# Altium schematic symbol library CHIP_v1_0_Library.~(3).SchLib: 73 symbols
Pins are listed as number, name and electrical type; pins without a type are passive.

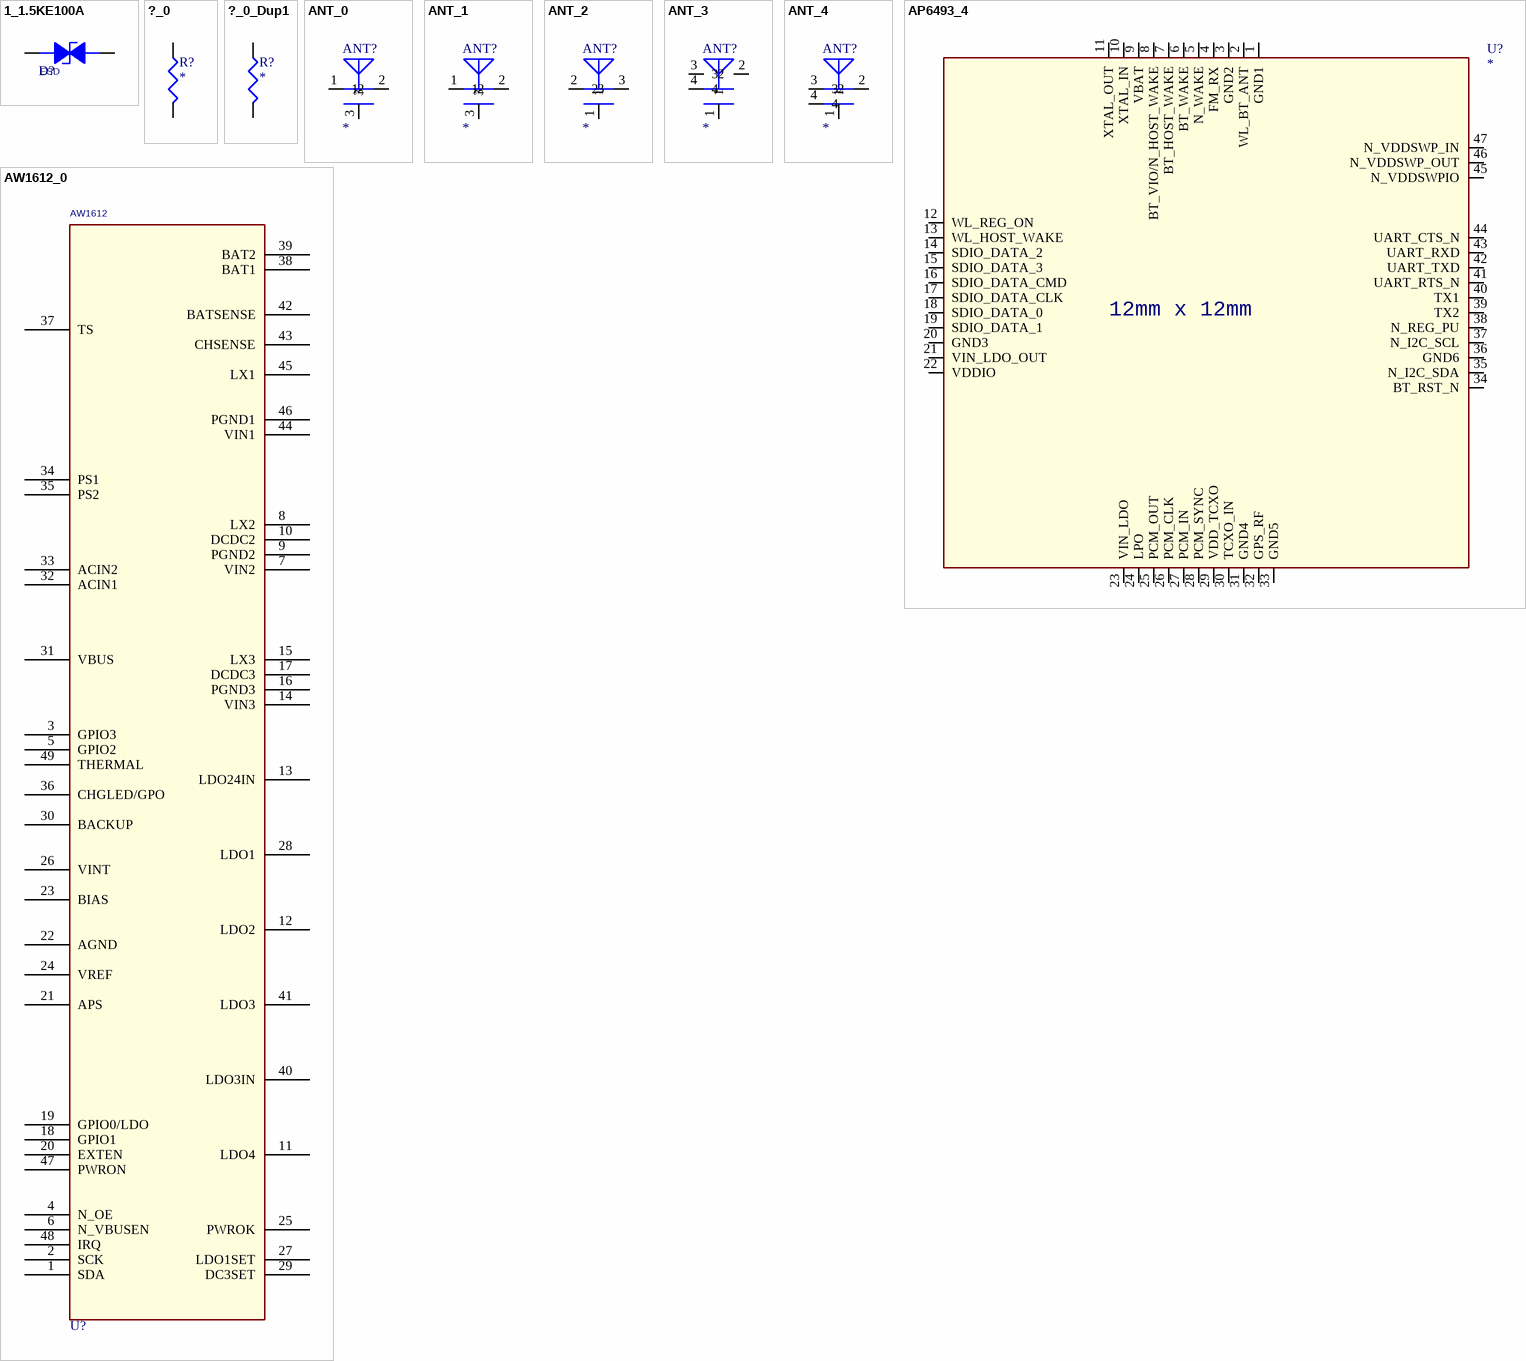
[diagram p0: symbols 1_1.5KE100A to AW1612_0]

## 1_1.5KE100A
designator D?, comment ESD
Altium-Right: 40; Altium-Bottom: 20
pins: 1 ANODE, 2 CATHODE

## ?_0
designator R?
Altium-Right: 20; Altium-Bottom: 30
footprint R0402
pins: 1, 2

## ?_0_Dup1
designator R?
Altium-Right: 20; Altium-Bottom: 30
footprint R0402
pins: 1, 2

## ANT_0
designator ANT?
Altium-Right: 20; Altium-Bottom: 30
pins: 1 (hiz), 2, 3

## ANT_1
designator ANT?
Altium-Right: 20; Altium-Bottom: 30
pins: 1, 2, 3

## ANT_2
designator ANT?
Altium-Right: 20; Altium-Bottom: 30
pins: 1, 2, 3

## ANT_3
designator ANT?
Altium-Right: 20; Altium-Bottom: 30
pins: 1, 2, 3, 4

## ANT_4
designator ANT?
Altium-Right: 20; Altium-Bottom: 30
pins: 1, 2, 3, 4

## AP6493_4
designator U?
Altium-Right: 350; Altium-Bottom: 340
pins: 1 GND1, 2 WL_BT_ANT, 3 GND2, 4 FM_RX, 5 N_WAKE, 6 BT_WAKE, 7 BT_HOST_WAKE, 8 BT_VIO/N_HOST_WAKE, 9 VBAT, 10 XTAL_IN, 11 XTAL_OUT, 12 WL_REG_ON, 13 WL_HOST_WAKE, 14 SDIO_DATA_2, 15 SDIO_DATA_3, 16 SDIO_DATA_CMD, 17 SDIO_DATA_CLK, 18 SDIO_DATA_0, 19 SDIO_DATA_1, 20 GND3, 21 VIN_LDO_OUT, 22 VDDIO, 23 VIN_LDO, 24 LPO, 25 PCM_OUT, 26 PCM_CLK, 27 PCM_IN, 28 PCM_SYNC, 29 VDD_TCXO, 30 TCXO_IN, 31 GND4, 32 GPS_RF, 33 GND5, 34 BT_RST_N, 35 N_I2C_SDA, 36 GND6, 37 N_I2C_SCL, 38 N_REG_PU, 39 TX2, 40 TX1, 41 UART_RTS_N, 42 UART_TXD, 43 UART_RXD, 44 UART_CTS_N, 45 N_VDDSWPIO, 46 N_VDDSWP_OUT, 47 N_VDDSWP_IN

## AW1612_0
designator U?, comment AW1612
Altium-Right: 130; Altium-Bottom: 730
pins: 1 SDA, 2 SCK, 3 GPIO3, 4 N_OE, 5 GPIO2, 6 N_VBUSEN, 7 VIN2, 8 LX2, 9 PGND2, 10 DCDC2, 11 LDO4, 12 LDO2, 13 LDO24IN, 14 VIN3, 15 LX3, 16 PGND3, 17 DCDC3, 18 GPIO1, 19 GPIO0/LDO, 20 EXTEN, 21 APS, 22 AGND, 23 BIAS, 24 VREF, 25 PWROK, 26 VINT, 27 LDO1SET, 28 LDO1, 29 DC3SET, 30 BACKUP, 31 VBUS, 32 ACIN1, 33 ACIN2, 34 PS1, 35 PS2, 36 CHGLED/GPO, 37 TS, 38 BAT1, 39 BAT2, 40 LDO3IN, 41 LDO3, 42 BATSENSE, 43 CHSENSE, 44 VIN1, 45 LX1, 46 PGND1, 47 PWRON, 48 IRQ, 49 THERMAL

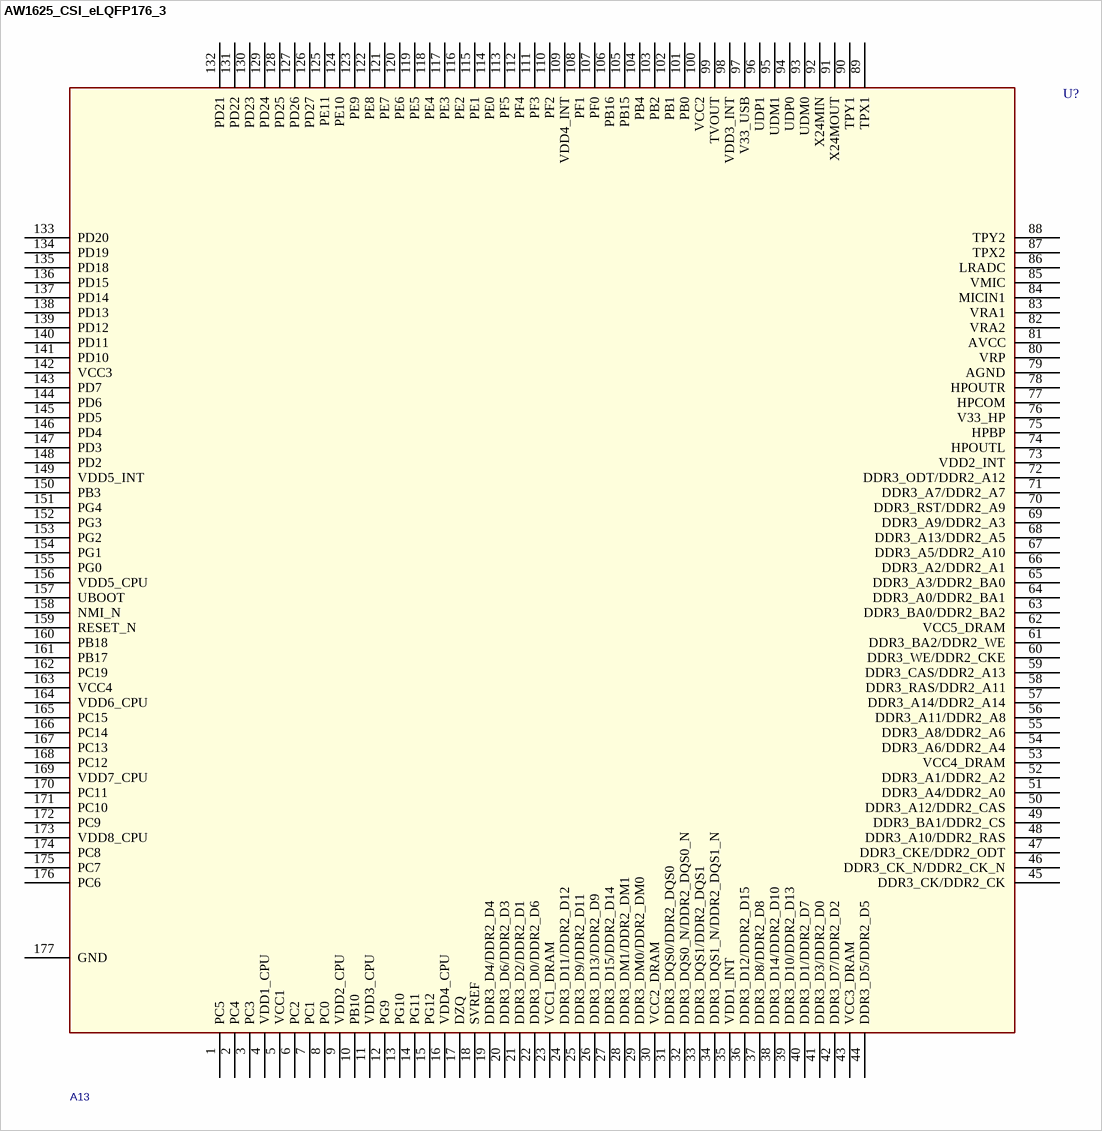
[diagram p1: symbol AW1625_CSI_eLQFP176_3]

## AW1625_CSI_eLQFP176_3
designator U?, comment A13
Altium-Right: 630
pins: 1 PC5, 2 PC4, 3 PC3, 4 VDD1_CPU, 5 VCC1, 6 PC2, 7 PC1, 8 PC0, 9 VDD2_CPU, 10 PB10, 11 VDD3_CPU, 12 PG9, 13 PG10, 14 PG11, 15 PG12, 16 VDD4_CPU, 17 DZQ, 18 SVREF, 19 DDR3_D4/DDR2_D4, 20 DDR3_D6/DDR2_D3, 21 DDR3_D2/DDR2_D1, 22 DDR3_D0/DDR2_D6, 23 VCC1_DRAM, 24 DDR3_D11/DDR2_D12, 25 DDR3_D9/DDR2_D11, 26 DDR3_D13/DDR2_D9, 27 DDR3_D15/DDR2_D14, 28 DDR3_DM1/DDR2_DM1, 29 DDR3_DM0/DDR2_DM0, 30 VCC2_DRAM, 31 DDR3_DQS0/DDR2_DQS0, 32 DDR3_DQS0_N/DDR2_DQS0_N, 33 DDR3_DQS1/DDR2_DQS1, 34 DDR3_DQS1_N/DDR2_DQS1_N, 35 VDD1_INT, 36 DDR3_D12/DDR2_D15, 37 DDR3_D8/DDR2_D8, 38 DDR3_D14/DDR2_D10, 39 DDR3_D10/DDR2_D13, 40 DDR3_D1/DDR2_D7, 41 DDR3_D3/DDR2_D0, 42 DDR3_D7/DDR2_D2, 43 VCC3_DRAM, 44 DDR3_D5/DDR2_D5, 45 DDR3_CK/DDR2_CK, 46 DDR3_CK_N/DDR2_CK_N, 47 DDR3_CKE/DDR2_ODT, 48 DDR3_A10/DDR2_RAS, 49 DDR3_BA1/DDR2_CS, 50 DDR3_A12/DDR2_CAS, 51 DDR3_A4/DDR2_A0, 52 DDR3_A1/DDR2_A2, 53 VCC4_DRAM, 54 DDR3_A6/DDR2_A4, 55 DDR3_A8/DDR2_A6, 56 DDR3_A11/DDR2_A8, 57 DDR3_A14/DDR2_A14, 58 DDR3_RAS/DDR2_A11, 59 DDR3_CAS/DDR2_A13, 60 DDR3_WE/DDR2_CKE, 61 DDR3_BA2/DDR2_WE, 62 VCC5_DRAM, 63 DDR3_BA0/DDR2_BA2, 64 DDR3_A0/DDR2_BA1, 65 DDR3_A3/DDR2_BA0, 66 DDR3_A2/DDR2_A1, 67 DDR3_A5/DDR2_A10, 68 DDR3_A13/DDR2_A5, 69 DDR3_A9/DDR2_A3, 70 DDR3_RST/DDR2_A9, 71 DDR3_A7/DDR2_A7, 72 DDR3_ODT/DDR2_A12, 73 VDD2_INT, 74 HPOUTL, 75 HPBP, 76 V33_HP, 77 HPCOM, 78 HPOUTR, 79 AGND, 80 VRP, 81 AVCC, 82 VRA2, 83 VRA1, 84 MICIN1, 85 VMIC, 86 LRADC, 87 TPX2, 88 TPY2, 89 TPX1, 90 TPY1, 91 X24MOUT, 92 X24MIN, 93 UDM0, 94 UDP0, 95 UDM1, 96 UDP1, 97 V33_USB, 98 VDD3_INT, 99 TVOUT, 100 VCC2, 101 PB0, 102 PB1, 103 PB2, 104 PB4, 105 PB15, 106 PB16, 107 PF0, 108 PF1, 109 VDD4_INT, 110 PF2, 111 PF3, 112 PF4, 113 PF5, 114 PE0, 115 PE1, 116 PE2, 117 PE3, 118 PE4, 119 PE5, 120 PE6, 121 PE7, 122 PE8, 123 PE9, 124 PE10, 125 PE11, 126 PD27, 127 PD26, 128 PD25, 129 PD24, 130 PD23, 131 PD22, 132 PD21, 133 PD20, 134 PD19, 135 PD18, 136 PD15, 137 PD14, 138 PD13, 139 PD12, 140 PD11, 141 PD10, 142 VCC3, 143 PD7, 144 PD6, 145 PD5, 146 PD4, 147 PD3, 148 PD2, 149 VDD5_INT, 150 PB3, 151 PG4, 152 PG3, 153 PG2, 154 PG1, 155 PG0, 156 VDD5_CPU, 157 UBOOT, 158 NMI_N, 159 RESET_N, 160 PB18, 161 PB17, 162 PC19, 163 VCC4, 164 VDD6_CPU, 165 PC15, 166 PC14, 167 PC13, 168 PC12, 169 VDD7_CPU, 170 PC11, 171 PC10, 172 PC9, 173 VDD8_CPU, 174 PC8, 175 PC7, 176 PC6, 177 GND

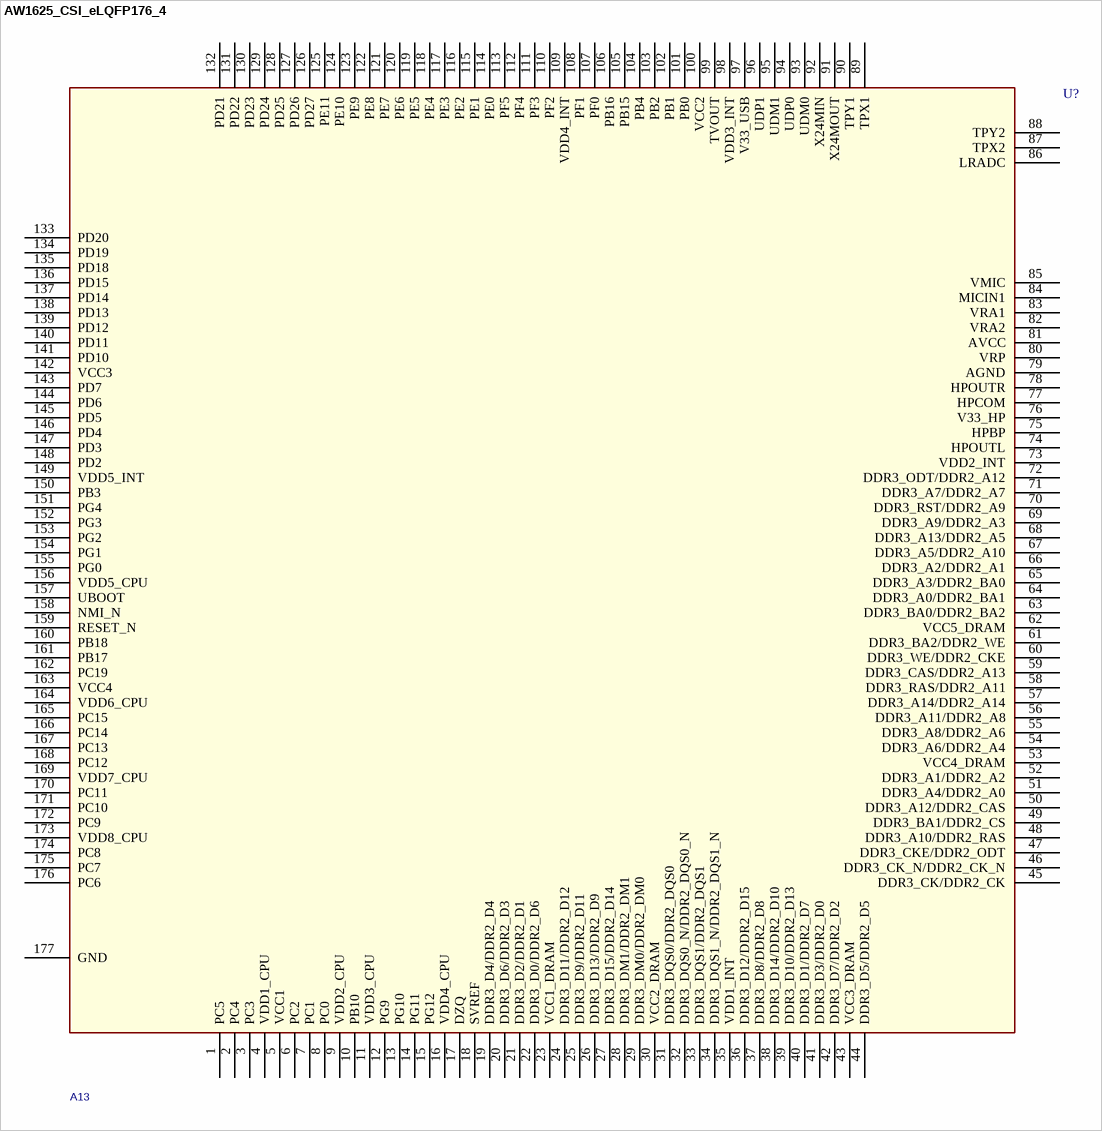
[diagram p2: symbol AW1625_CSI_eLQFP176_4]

## AW1625_CSI_eLQFP176_4
designator U?, comment A13
Altium-Right: 630
pins: 1 PC5, 2 PC4, 3 PC3, 4 VDD1_CPU, 5 VCC1, 6 PC2, 7 PC1, 8 PC0, 9 VDD2_CPU, 10 PB10, 11 VDD3_CPU, 12 PG9, 13 PG10, 14 PG11, 15 PG12, 16 VDD4_CPU, 17 DZQ, 18 SVREF, 19 DDR3_D4/DDR2_D4, 20 DDR3_D6/DDR2_D3, 21 DDR3_D2/DDR2_D1, 22 DDR3_D0/DDR2_D6, 23 VCC1_DRAM, 24 DDR3_D11/DDR2_D12, 25 DDR3_D9/DDR2_D11, 26 DDR3_D13/DDR2_D9, 27 DDR3_D15/DDR2_D14, 28 DDR3_DM1/DDR2_DM1, 29 DDR3_DM0/DDR2_DM0, 30 VCC2_DRAM, 31 DDR3_DQS0/DDR2_DQS0, 32 DDR3_DQS0_N/DDR2_DQS0_N, 33 DDR3_DQS1/DDR2_DQS1, 34 DDR3_DQS1_N/DDR2_DQS1_N, 35 VDD1_INT, 36 DDR3_D12/DDR2_D15, 37 DDR3_D8/DDR2_D8, 38 DDR3_D14/DDR2_D10, 39 DDR3_D10/DDR2_D13, 40 DDR3_D1/DDR2_D7, 41 DDR3_D3/DDR2_D0, 42 DDR3_D7/DDR2_D2, 43 VCC3_DRAM, 44 DDR3_D5/DDR2_D5, 45 DDR3_CK/DDR2_CK, 46 DDR3_CK_N/DDR2_CK_N, 47 DDR3_CKE/DDR2_ODT, 48 DDR3_A10/DDR2_RAS, 49 DDR3_BA1/DDR2_CS, 50 DDR3_A12/DDR2_CAS, 51 DDR3_A4/DDR2_A0, 52 DDR3_A1/DDR2_A2, 53 VCC4_DRAM, 54 DDR3_A6/DDR2_A4, 55 DDR3_A8/DDR2_A6, 56 DDR3_A11/DDR2_A8, 57 DDR3_A14/DDR2_A14, 58 DDR3_RAS/DDR2_A11, 59 DDR3_CAS/DDR2_A13, 60 DDR3_WE/DDR2_CKE, 61 DDR3_BA2/DDR2_WE, 62 VCC5_DRAM, 63 DDR3_BA0/DDR2_BA2, 64 DDR3_A0/DDR2_BA1, 65 DDR3_A3/DDR2_BA0, 66 DDR3_A2/DDR2_A1, 67 DDR3_A5/DDR2_A10, 68 DDR3_A13/DDR2_A5, 69 DDR3_A9/DDR2_A3, 70 DDR3_RST/DDR2_A9, 71 DDR3_A7/DDR2_A7, 72 DDR3_ODT/DDR2_A12, 73 VDD2_INT, 74 HPOUTL, 75 HPBP, 76 V33_HP, 77 HPCOM, 78 HPOUTR, 79 AGND, 80 VRP, 81 AVCC, 82 VRA2, 83 VRA1, 84 MICIN1, 85 VMIC, 86 LRADC, 87 TPX2, 88 TPY2, 89 TPX1, 90 TPY1, 91 X24MOUT, 92 X24MIN, 93 UDM0, 94 UDP0, 95 UDM1, 96 UDP1, 97 V33_USB, 98 VDD3_INT, 99 TVOUT, 100 VCC2, 101 PB0, 102 PB1, 103 PB2, 104 PB4, 105 PB15, 106 PB16, 107 PF0, 108 PF1, 109 VDD4_INT, 110 PF2, 111 PF3, 112 PF4, 113 PF5, 114 PE0, 115 PE1, 116 PE2, 117 PE3, 118 PE4, 119 PE5, 120 PE6, 121 PE7, 122 PE8, 123 PE9, 124 PE10, 125 PE11, 126 PD27, 127 PD26, 128 PD25, 129 PD24, 130 PD23, 131 PD22, 132 PD21, 133 PD20, 134 PD19, 135 PD18, 136 PD15, 137 PD14, 138 PD13, 139 PD12, 140 PD11, 141 PD10, 142 VCC3, 143 PD7, 144 PD6, 145 PD5, 146 PD4, 147 PD3, 148 PD2, 149 VDD5_INT, 150 PB3, 151 PG4, 152 PG3, 153 PG2, 154 PG1, 155 PG0, 156 VDD5_CPU, 157 UBOOT, 158 NMI_N, 159 RESET_N, 160 PB18, 161 PB17, 162 PC19, 163 VCC4, 164 VDD6_CPU, 165 PC15, 166 PC14, 167 PC13, 168 PC12, 169 VDD7_CPU, 170 PC11, 171 PC10, 172 PC9, 173 VDD8_CPU, 174 PC8, 175 PC7, 176 PC6, 177 GND

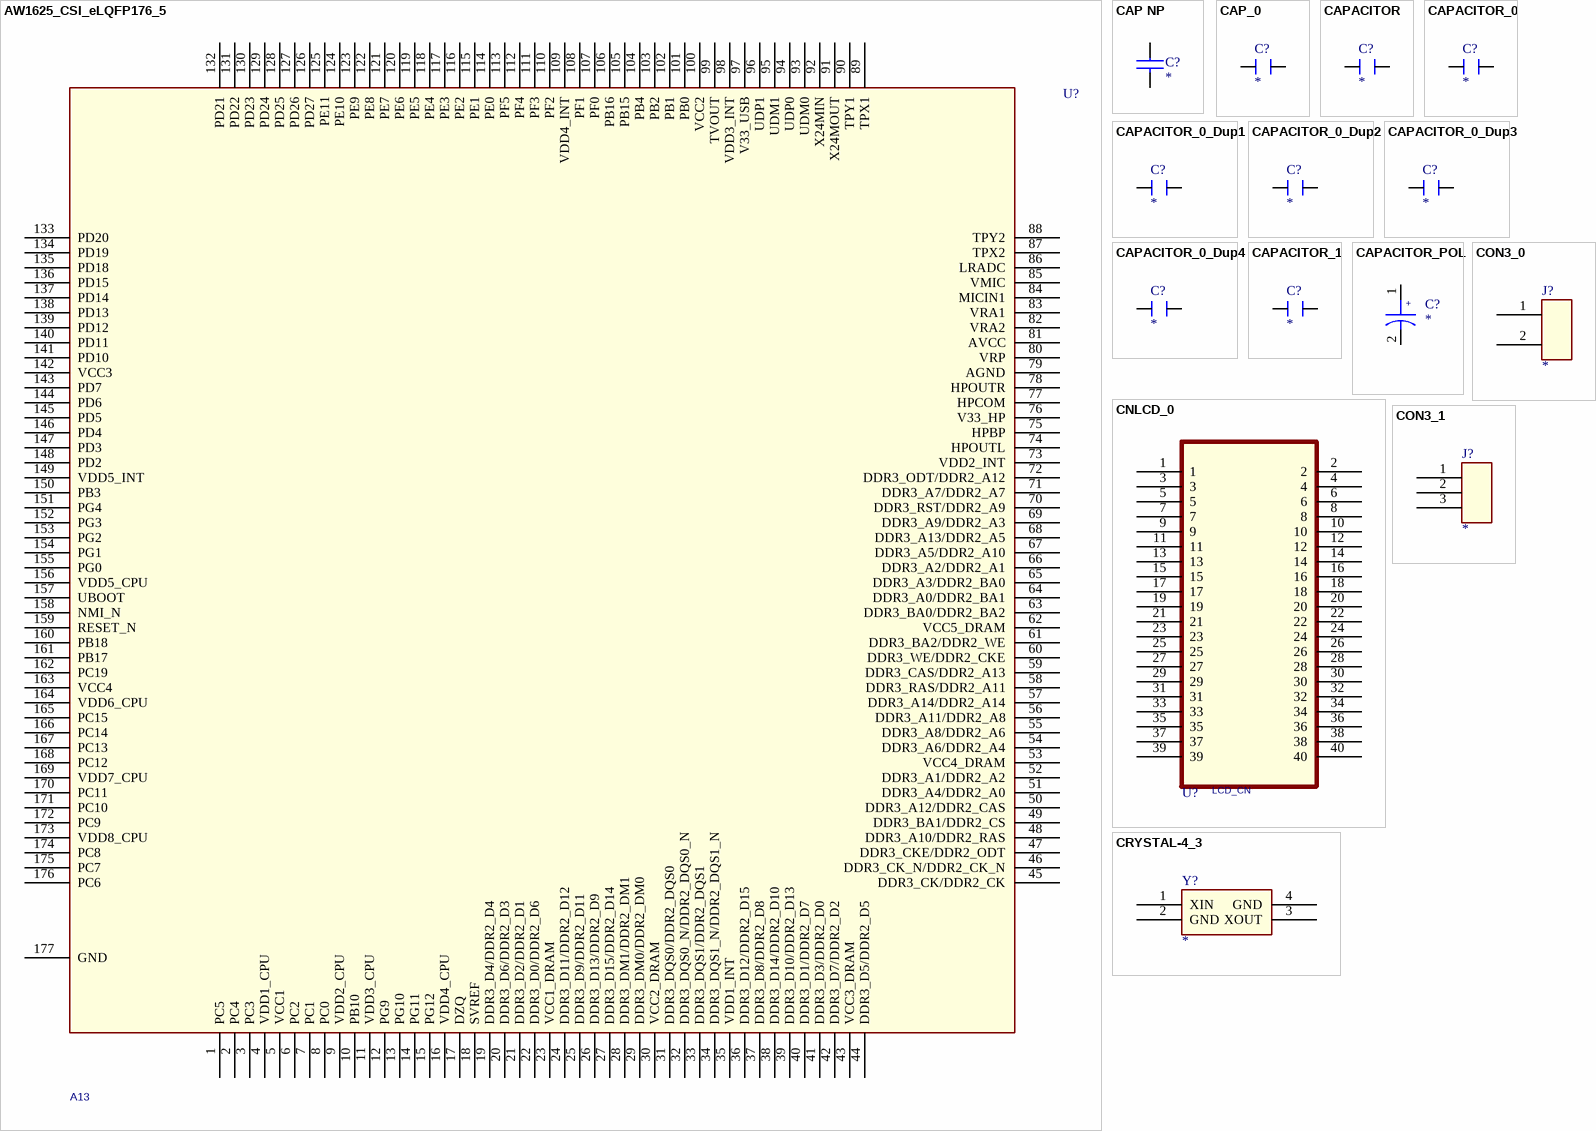
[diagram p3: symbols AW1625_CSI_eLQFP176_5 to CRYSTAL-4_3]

## AW1625_CSI_eLQFP176_5
designator U?, comment A13
Altium-Right: 630
pins: 1 PC5, 2 PC4, 3 PC3, 4 VDD1_CPU, 5 VCC1, 6 PC2, 7 PC1, 8 PC0, 9 VDD2_CPU, 10 PB10, 11 VDD3_CPU, 12 PG9, 13 PG10, 14 PG11, 15 PG12, 16 VDD4_CPU, 17 DZQ, 18 SVREF, 19 DDR3_D4/DDR2_D4, 20 DDR3_D6/DDR2_D3, 21 DDR3_D2/DDR2_D1, 22 DDR3_D0/DDR2_D6, 23 VCC1_DRAM, 24 DDR3_D11/DDR2_D12, 25 DDR3_D9/DDR2_D11, 26 DDR3_D13/DDR2_D9, 27 DDR3_D15/DDR2_D14, 28 DDR3_DM1/DDR2_DM1, 29 DDR3_DM0/DDR2_DM0, 30 VCC2_DRAM, 31 DDR3_DQS0/DDR2_DQS0, 32 DDR3_DQS0_N/DDR2_DQS0_N, 33 DDR3_DQS1/DDR2_DQS1, 34 DDR3_DQS1_N/DDR2_DQS1_N, 35 VDD1_INT, 36 DDR3_D12/DDR2_D15, 37 DDR3_D8/DDR2_D8, 38 DDR3_D14/DDR2_D10, 39 DDR3_D10/DDR2_D13, 40 DDR3_D1/DDR2_D7, 41 DDR3_D3/DDR2_D0, 42 DDR3_D7/DDR2_D2, 43 VCC3_DRAM, 44 DDR3_D5/DDR2_D5, 45 DDR3_CK/DDR2_CK, 46 DDR3_CK_N/DDR2_CK_N, 47 DDR3_CKE/DDR2_ODT, 48 DDR3_A10/DDR2_RAS, 49 DDR3_BA1/DDR2_CS, 50 DDR3_A12/DDR2_CAS, 51 DDR3_A4/DDR2_A0, 52 DDR3_A1/DDR2_A2, 53 VCC4_DRAM, 54 DDR3_A6/DDR2_A4, 55 DDR3_A8/DDR2_A6, 56 DDR3_A11/DDR2_A8, 57 DDR3_A14/DDR2_A14, 58 DDR3_RAS/DDR2_A11, 59 DDR3_CAS/DDR2_A13, 60 DDR3_WE/DDR2_CKE, 61 DDR3_BA2/DDR2_WE, 62 VCC5_DRAM, 63 DDR3_BA0/DDR2_BA2, 64 DDR3_A0/DDR2_BA1, 65 DDR3_A3/DDR2_BA0, 66 DDR3_A2/DDR2_A1, 67 DDR3_A5/DDR2_A10, 68 DDR3_A13/DDR2_A5, 69 DDR3_A9/DDR2_A3, 70 DDR3_RST/DDR2_A9, 71 DDR3_A7/DDR2_A7, 72 DDR3_ODT/DDR2_A12, 73 VDD2_INT, 74 HPOUTL, 75 HPBP, 76 V33_HP, 77 HPCOM, 78 HPOUTR, 79 AGND, 80 VRP, 81 AVCC, 82 VRA2, 83 VRA1, 84 MICIN1, 85 VMIC, 86 LRADC, 87 TPX2, 88 TPY2, 89 TPX1, 90 TPY1, 91 X24MOUT, 92 X24MIN, 93 UDM0, 94 UDP0, 95 UDM1, 96 UDP1, 97 V33_USB, 98 VDD3_INT, 99 TVOUT, 100 VCC2, 101 PB0, 102 PB1, 103 PB2, 104 PB4, 105 PB15, 106 PB16, 107 PF0, 108 PF1, 109 VDD4_INT, 110 PF2, 111 PF3, 112 PF4, 113 PF5, 114 PE0, 115 PE1, 116 PE2, 117 PE3, 118 PE4, 119 PE5, 120 PE6, 121 PE7, 122 PE8, 123 PE9, 124 PE10, 125 PE11, 126 PD27, 127 PD26, 128 PD25, 129 PD24, 130 PD23, 131 PD22, 132 PD21, 133 PD20, 134 PD19, 135 PD18, 136 PD15, 137 PD14, 138 PD13, 139 PD12, 140 PD11, 141 PD10, 142 VCC3, 143 PD7, 144 PD6, 145 PD5, 146 PD4, 147 PD3, 148 PD2, 149 VDD5_INT, 150 PB3, 151 PG4, 152 PG3, 153 PG2, 154 PG1, 155 PG0, 156 VDD5_CPU, 157 UBOOT, 158 NMI_N, 159 RESET_N, 160 PB18, 161 PB17, 162 PC19, 163 VCC4, 164 VDD6_CPU, 165 PC15, 166 PC14, 167 PC13, 168 PC12, 169 VDD7_CPU, 170 PC11, 171 PC10, 172 PC9, 173 VDD8_CPU, 174 PC8, 175 PC7, 176 PC6, 177 GND

## CAP NP
designator C?
Altium-Right: 20; Altium-Bottom: 10
pins: 1, 2

## CAP_0
designator C?
Altium-Right: 10; Altium-Bottom: 20
footprint 0805
pins: 1, 2

## CAPACITOR
designator C?
Altium-Right: 10; Altium-Bottom: 20
pins: 1, 2

## CAPACITOR_0
designator C?
Altium-Right: 10; Altium-Bottom: 20
pins: 1, 2

## CAPACITOR_0_Dup1
designator C?
Altium-Right: 10; Altium-Bottom: 20
pins: 1, 2

## CAPACITOR_0_Dup2
designator C?
Altium-Right: 10; Altium-Bottom: 20
pins: 1, 2

## CAPACITOR_0_Dup3
designator C?
Altium-Right: 10; Altium-Bottom: 20
pins: 1, 2

## CAPACITOR_0_Dup4
designator C?
Altium-Right: 10; Altium-Bottom: 20
pins: 1, 2

## CAPACITOR_1
designator C?
Altium-Right: 10; Altium-Bottom: 20
pins: 1, 2

## CAPACITOR_POL
designator C?
Altium-Right: 20
pins: 1, 2

## CNLCD_0
designator U?, comment LCD_CN
Altium-Right: 90; Altium-Bottom: 230
pins: 1, 2, 3, 4, 5, 6, 7, 8, 9, 10, 11, 12, 13, 14, 15, 16, 17, 18, 19, 20, 21, 22, 23, 24, 25, 26, 27, 28, 29, 30, 31, 32, 33, 34, 35, 36, 37, 38, 39, 40

## CON3_0
designator J?
Altium-Right: 20; Altium-Bottom: 40
pins: 1, 2

## CON3_1
designator J?
Altium-Right: 20; Altium-Bottom: 40
pins: 1, 2, 3

## CRYSTAL-4_3
designator Y?
Altium-Right: 60; Altium-Bottom: 30
footprint CRY-3225
pins: 1 XIN, 2 GND (power), 3 XOUT, 4 GND (power)

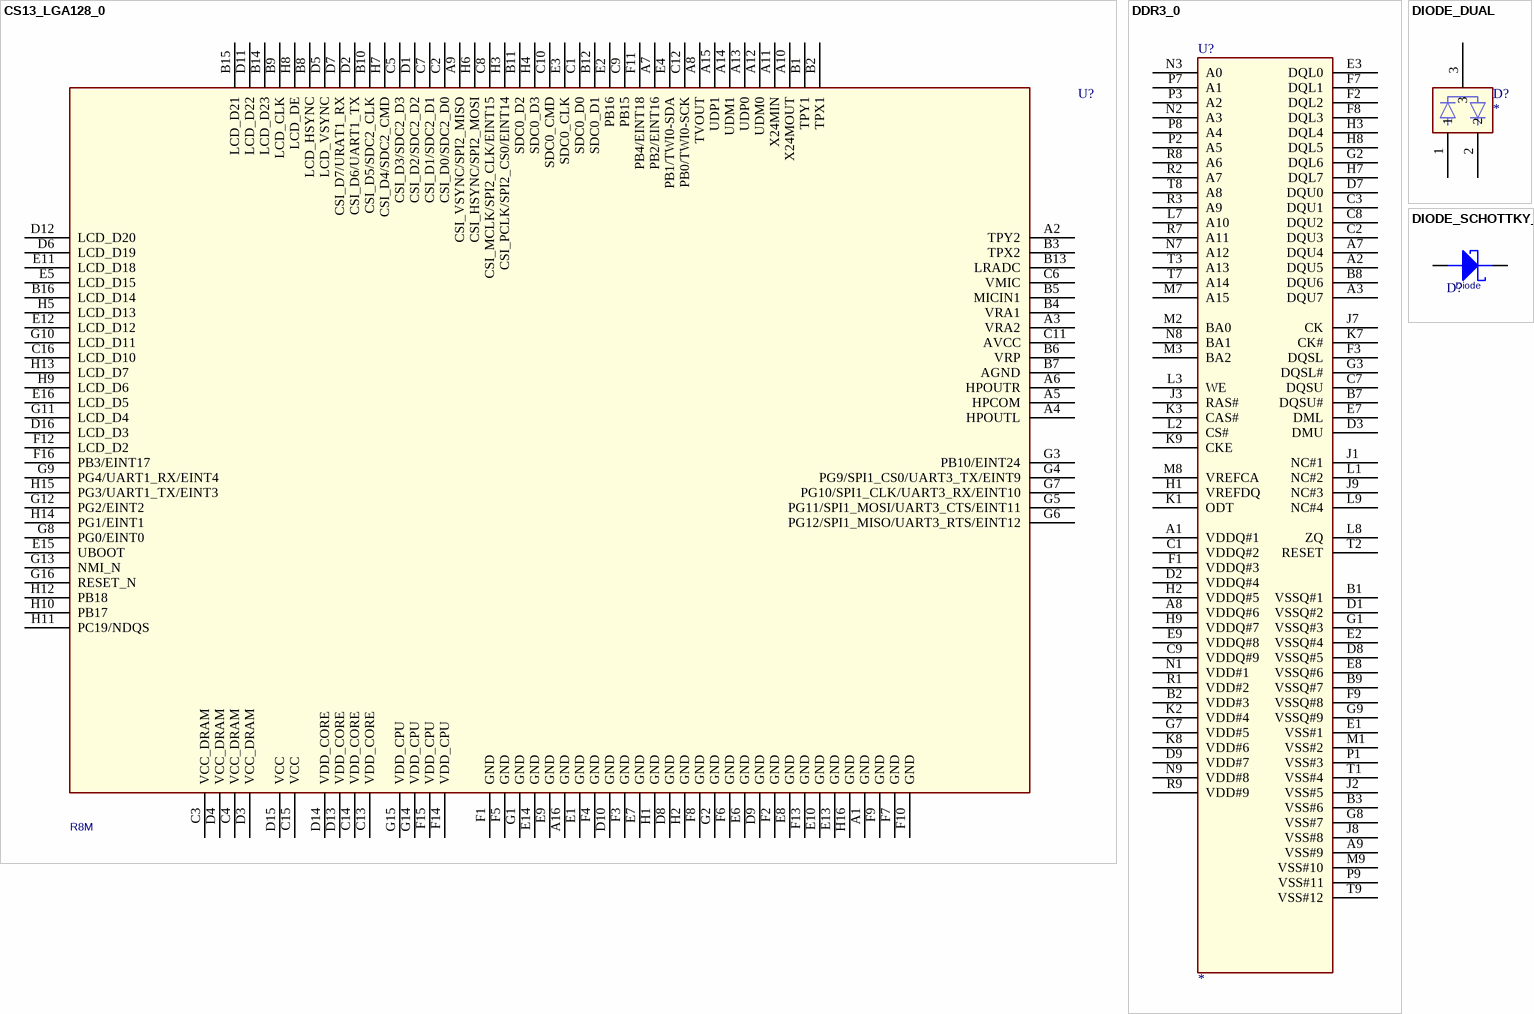
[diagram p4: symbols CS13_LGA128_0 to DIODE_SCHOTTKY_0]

## CS13_LGA128_0
designator U?, comment R8M
Altium-Right: 640; Altium-Bottom: 470
pins: A1 GND (power), A2 TPY2, A3 VRA2, A4 HPOUTL, A5 HPCOM, A6 HPOUTR, A7 PB2/EINT16, A8 TVOUT, A9 CSI_VSYNC/SPI2_MISO, A10 X24MOUT, A11 X24MIN, A12 UDM0, A13 UDP0, A14 UDM1, A15 UDP1, A16 GND (power), B1 TPY1, B2 TPX1, B3 TPX2, B4 VRA1, B5 MICIN1, B6 VRP, B7 AGND, B8 LCD_HSYNC, B9 LCD_CLK, B10 CSI_D5/SDC2_CLK, B11 SDC0_D2, B12 SDC0_D1, B13 LRADC, B14 LCD_D23, B15 LCD_D21, B16 LCD_D14, C1 SDC0_D0, C2 CSI_D0/SDC2_D0, C3 VCC_DRAM (power), C4 VCC_DRAM (power), C5 CSI_D3/SDC2_D3, C6 VMIC, C7 CSI_D1/SDC2_D1, C8 CSI_MCLK/SPI2_CLK/EINT15, C9 PB15, C10 SDC0_CMD, C11 AVCC, C12 PB0/TWI0-SCK, C13 VDD_CORE (power), C14 VDD_CORE (power), C15 VCC (power), C16 LCD_D10, D1 CSI_D2/SDC2_D2, D2 CSI_D6/UART1_TX, D3 VCC_DRAM (power), D4 VCC_DRAM (power), D5 LCD_VSYNC, D6 LCD_D19, D7 CSI_D7/URAT1_RX, D8 GND (power), D9 GND (power), D10 GND (power), D11 LCD_D22, D12 LCD_D20, D13 VDD_CORE (power), D14 VDD_CORE (power), D15 VCC (power), D16 LCD_D3, E1 GND (power), E2 PB16, E3 SDC0_CLK, E4 PB1/TWI0-SDA, E5 LCD_D15, E6 GND (power), E7 GND (power), E8 GND (power), E9 GND (power), E10 GND (power), E11 LCD_D18, E12 LCD_D12, E13 GND (power), E14 GND (power), E15 UBOOT, E16 LCD_D5, F1 GND (power), F2 GND (power), F3 GND (power), F4 GND (power), F5 GND (power), F6 GND (power), F7 GND (power), F8 GND (power), F9 GND (power), F10 GND (power), F11 PB4/EINT18, F12 LCD_D2, F13 GND (power), F14 VDD_CPU (power), F15 VDD_CPU (power), F16 PB3/EINT17, G1 GND (power), G2 GND (power), G3 PB10/EINT24, G4 PG9/SPI1_CS0/UART3_TX/EINT9, G5 PG11/SPI1_MOSI/UART3_CTS/EINT11, G6 PG12/SPI1_MISO/UART3_RTS/EINT12, G7 PG10/SPI1_CLK/UART3_RX/EINT10, G8 PG0/EINT0, G9 PG4/UART1_RX/EINT4, G10 LCD_D11, G11 LCD_D4, G12 PG2/EINT2, G13 NMI_N, G14 VDD_CPU (power), G15 VDD_CPU (power), G16 RESET_N, H1 GND (power), H2 GND (power), H3 CSI_PCLK/SPI2_CS0/EINT14, H4 SDC0_D3, H5 LCD_D13, H6 CSI_HSYNC/SPI2_MOSI, H7 CSI_D4/SDC2_CMD, H8 LCD_DE, H9 LCD_D6, H10 PB17, H11 PC19/NDQS, H12 PB18, H13 LCD_D7, H14 PG1/EINT1, H15 PG3/UART1_TX/EINT3, H16 GND (power)

## DDR3_0
designator U?
Altium-Right: 90; Altium-Bottom: 610
pins: A1 VDDQ#1, A2 DQU5, A3 DQU7, A7 DQU4, A8 VDDQ#6, A9 VSS#9, B1 VSSQ#1, B2 VDD#3, B3 VSS#6, B7 DQSU#, B8 DQU6, B9 VSSQ#7, C1 VDDQ#2, C2 DQU3, C3 DQU1, C7 DQSU, C8 DQU2, C9 VDDQ#9, D1 VSSQ#2, D2 VDDQ#4, D3 DMU, D7 DQU0, D8 VSSQ#5, D9 VDD#7, E1 VSS#1, E2 VSSQ#4, E3 DQL0, E7 DML, E8 VSSQ#6, E9 VDDQ#8, F1 VDDQ#3, F2 DQL2, F3 DQSL, F7 DQL1, F8 DQL3, F9 VSSQ#8, G1 VSSQ#3, G2 DQL6, G3 DQSL#, G7 VDD#5, G8 VSS#7, G9 VSSQ#9, H1 VREFDQ, H2 VDDQ#5, H3 DQL4, H7 DQL7, H8 DQL5, H9 VDDQ#7, J1 NC#1, J2 VSS#5, J3 RAS#, J7 CK, J8 VSS#8, J9 NC#3, K1 ODT, K2 VDD#4, K3 CAS#, K7 CK#, K8 VDD#6, K9 CKE, L1 NC#2, L2 CS#, L3 WE, L7 A10, L8 ZQ, L9 NC#4, M1 VSS#2, M2 BA0, M3 BA2, M7 A15, M8 VREFCA, M9 VSS#10, N1 VDD#1, N2 A3, N3 A0, N7 A12, N8 BA1, N9 VDD#8, P1 VSS#3, P2 A5, P3 A2, P7 A1, P8 A4, P9 VSS#11, R1 VDD#2, R2 A7, R3 A9, R7 A11, R8 A6, R9 VDD#9, T1 VSS#4, T2 RESET, T3 A13, T7 A14, T8 A8, T9 VSS#12

## DIODE_DUAL
designator D?
Altium-Right: 40; Altium-Bottom: 30
pins: 1, 2, 3

## DIODE_SCHOTTKY_0
designator D?, comment Diode
Altium-Right: 30; Altium-Bottom: 20
footprint SOD123
pins: 1, 2

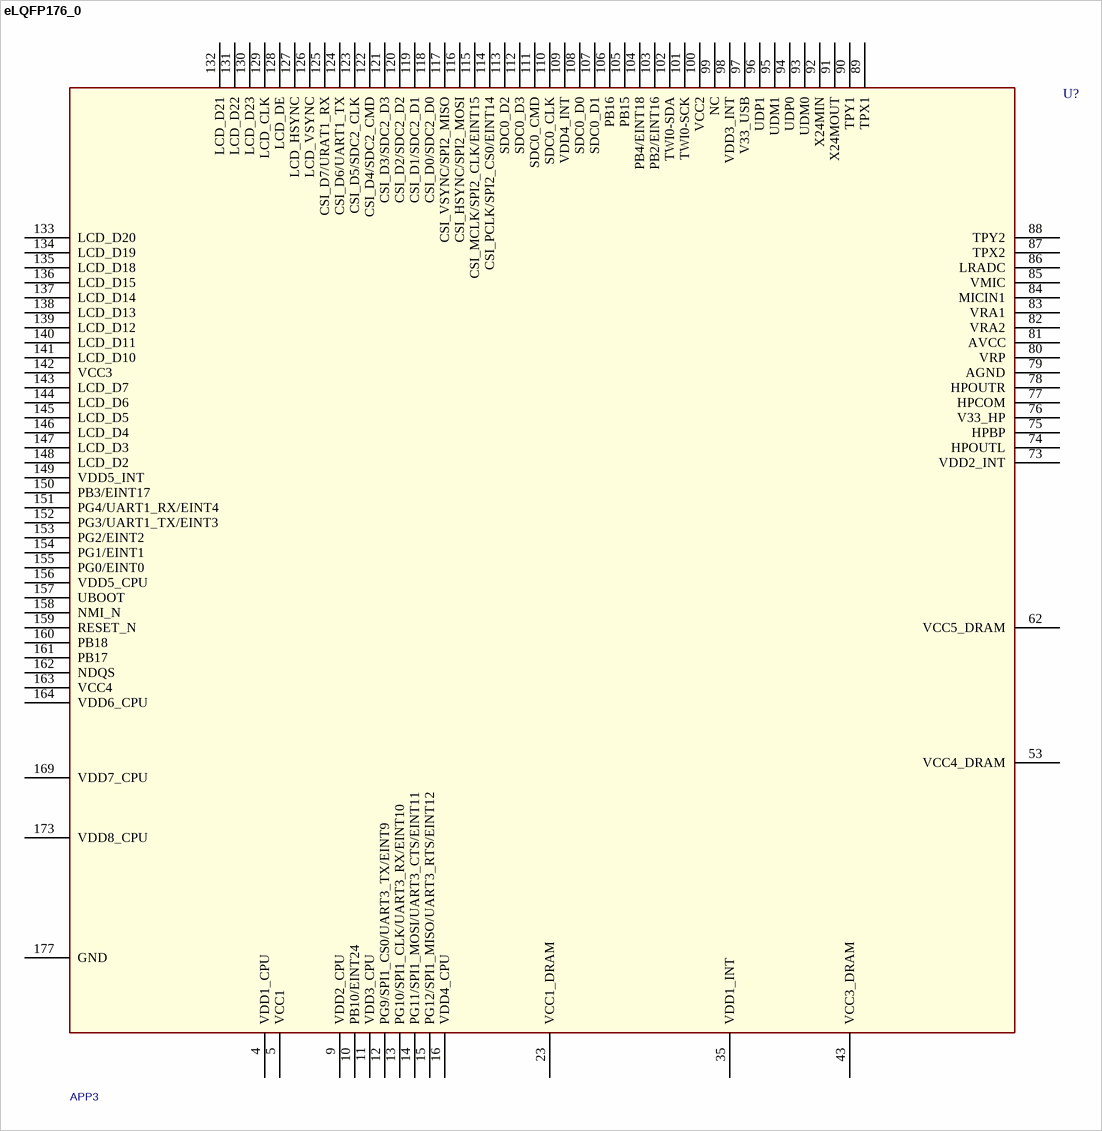
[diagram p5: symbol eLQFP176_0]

## eLQFP176_0
designator U?, comment APP3
Altium-Right: 630
pins: 4 VDD1_CPU, 5 VCC1, 9 VDD2_CPU, 10 PB10/EINT24, 11 VDD3_CPU, 12 PG9/SPI1_CS0/UART3_TX/EINT9, 13 PG10/SPI1_CLK/UART3_RX/EINT10, 14 PG11/SPI1_MOSI/UART3_CTS/EINT11, 15 PG12/SPI1_MISO/UART3_RTS/EINT12, 16 VDD4_CPU, 23 VCC1_DRAM, 35 VDD1_INT, 43 VCC3_DRAM, 53 VCC4_DRAM, 62 VCC5_DRAM, 73 VDD2_INT, 74 HPOUTL, 75 HPBP, 76 V33_HP, 77 HPCOM, 78 HPOUTR, 79 AGND, 80 VRP, 81 AVCC, 82 VRA2, 83 VRA1, 84 MICIN1, 85 VMIC, 86 LRADC, 87 TPX2, 88 TPY2, 89 TPX1, 90 TPY1, 91 X24MOUT, 92 X24MIN, 93 UDM0, 94 UDP0, 95 UDM1, 96 UDP1, 97 V33_USB, 98 VDD3_INT, 99 NC, 100 VCC2, 101 TWI0-SCK, 102 TWI0-SDA, 103 PB2/EINT16, 104 PB4/EINT18, 105 PB15, 106 PB16, 107 SDC0_D1, 108 SDC0_D0, 109 VDD4_INT, 110 SDC0_CLK, 111 SDC0_CMD, 112 SDC0_D3, 113 SDC0_D2, 114 CSI_PCLK/SPI2_CS0/EINT14, 115 CSI_MCLK/SPI2_CLK/EINT15, 116 CSI_HSYNC/SPI2_MOSI, 117 CSI_VSYNC/SPI2_MISO, 118 CSI_D0/SDC2_D0, 119 CSI_D1/SDC2_D1, 120 CSI_D2/SDC2_D2, 121 CSI_D3/SDC2_D3, 122 CSI_D4/SDC2_CMD, 123 CSI_D5/SDC2_CLK, 124 CSI_D6/UART1_TX, 125 CSI_D7/URAT1_RX, 126 LCD_VSYNC, 127 LCD_HSYNC, 128 LCD_DE, 129 LCD_CLK, 130 LCD_D23, 131 LCD_D22, 132 LCD_D21, 133 LCD_D20, 134 LCD_D19, 135 LCD_D18, 136 LCD_D15, 137 LCD_D14, 138 LCD_D13, 139 LCD_D12, 140 LCD_D11, 141 LCD_D10, 142 VCC3, 143 LCD_D7, 144 LCD_D6, 145 LCD_D5, 146 LCD_D4, 147 LCD_D3, 148 LCD_D2, 149 VDD5_INT, 150 PB3/EINT17, 151 PG4/UART1_RX/EINT4, 152 PG3/UART1_TX/EINT3, 153 PG2/EINT2, 154 PG1/EINT1, 155 PG0/EINT0, 156 VDD5_CPU, 157 UBOOT, 158 NMI_N, 159 RESET_N, 160 PB18, 161 PB17, 162 NDQS, 163 VCC4, 164 VDD6_CPU, 169 VDD7_CPU, 173 VDD8_CPU, 177 GND

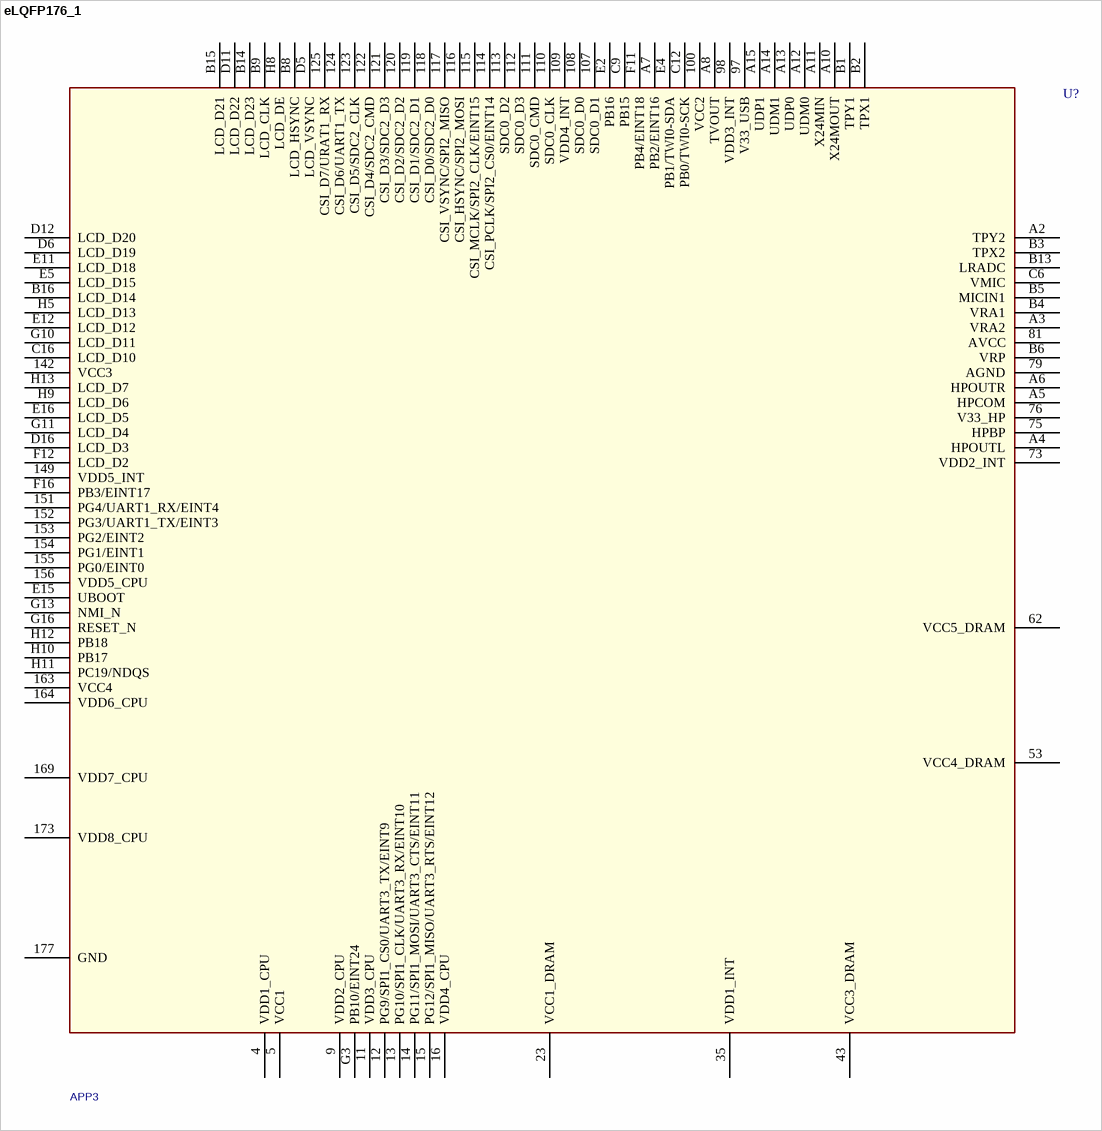
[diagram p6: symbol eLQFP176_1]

## eLQFP176_1
designator U?, comment APP3
Altium-Right: 630
pins: 4 VDD1_CPU, 5 VCC1, 9 VDD2_CPU, 11 VDD3_CPU, 12 PG9/SPI1_CS0/UART3_TX/EINT9, 13 PG10/SPI1_CLK/UART3_RX/EINT10, 14 PG11/SPI1_MOSI/UART3_CTS/EINT11, 15 PG12/SPI1_MISO/UART3_RTS/EINT12, 16 VDD4_CPU, 23 VCC1_DRAM, 35 VDD1_INT, 43 VCC3_DRAM, 53 VCC4_DRAM, 62 VCC5_DRAM, 73 VDD2_INT, 75 HPBP, 76 V33_HP, 79 AGND, 81 AVCC, 97 V33_USB, 98 VDD3_INT, 100 VCC2, 107 SDC0_D1, 108 SDC0_D0, 109 VDD4_INT, 110 SDC0_CLK, 111 SDC0_CMD, 112 SDC0_D3, 113 SDC0_D2, 114 CSI_PCLK/SPI2_CS0/EINT14, 115 CSI_MCLK/SPI2_CLK/EINT15, 116 CSI_HSYNC/SPI2_MOSI, 117 CSI_VSYNC/SPI2_MISO, 118 CSI_D0/SDC2_D0, 119 CSI_D1/SDC2_D1, 120 CSI_D2/SDC2_D2, 121 CSI_D3/SDC2_D3, 122 CSI_D4/SDC2_CMD, 123 CSI_D5/SDC2_CLK, 124 CSI_D6/UART1_TX, 125 CSI_D7/URAT1_RX, 142 VCC3, 149 VDD5_INT, 151 PG4/UART1_RX/EINT4, 152 PG3/UART1_TX/EINT3, 153 PG2/EINT2, 154 PG1/EINT1, 155 PG0/EINT0, 156 VDD5_CPU, 163 VCC4, 164 VDD6_CPU, 169 VDD7_CPU, 173 VDD8_CPU, 177 GND, A2 TPY2, A3 VRA2, A4 HPOUTL, A5 HPCOM, A6 HPOUTR, A7 PB2/EINT16, A8 TVOUT, A10 X24MOUT, A11 X24MIN, A12 UDM0, A13 UDP0, A14 UDM1, A15 UDP1, B1 TPY1, B2 TPX1, B3 TPX2, B4 VRA1, B5 MICIN1, B6 VRP, B8 LCD_HSYNC, B9 LCD_CLK, B13 LRADC, B14 LCD_D23, B15 LCD_D21, B16 LCD_D14, C6 VMIC, C9 PB15, C12 PB0/TWI0-SCK, C16 LCD_D10, D5 LCD_VSYNC, D6 LCD_D19, D11 LCD_D22, D12 LCD_D20, D16 LCD_D3, E2 PB16, E4 PB1/TWI0-SDA, E5 LCD_D15, E11 LCD_D18, E12 LCD_D12, E15 UBOOT, E16 LCD_D5, F11 PB4/EINT18, F12 LCD_D2, F16 PB3/EINT17, G3 PB10/EINT24, G10 LCD_D11, G11 LCD_D4, G13 NMI_N, G16 RESET_N, H5 LCD_D13, H8 LCD_DE, H9 LCD_D6, H10 PB17, H11 PC19/NDQS, H12 PB18, H13 LCD_D7

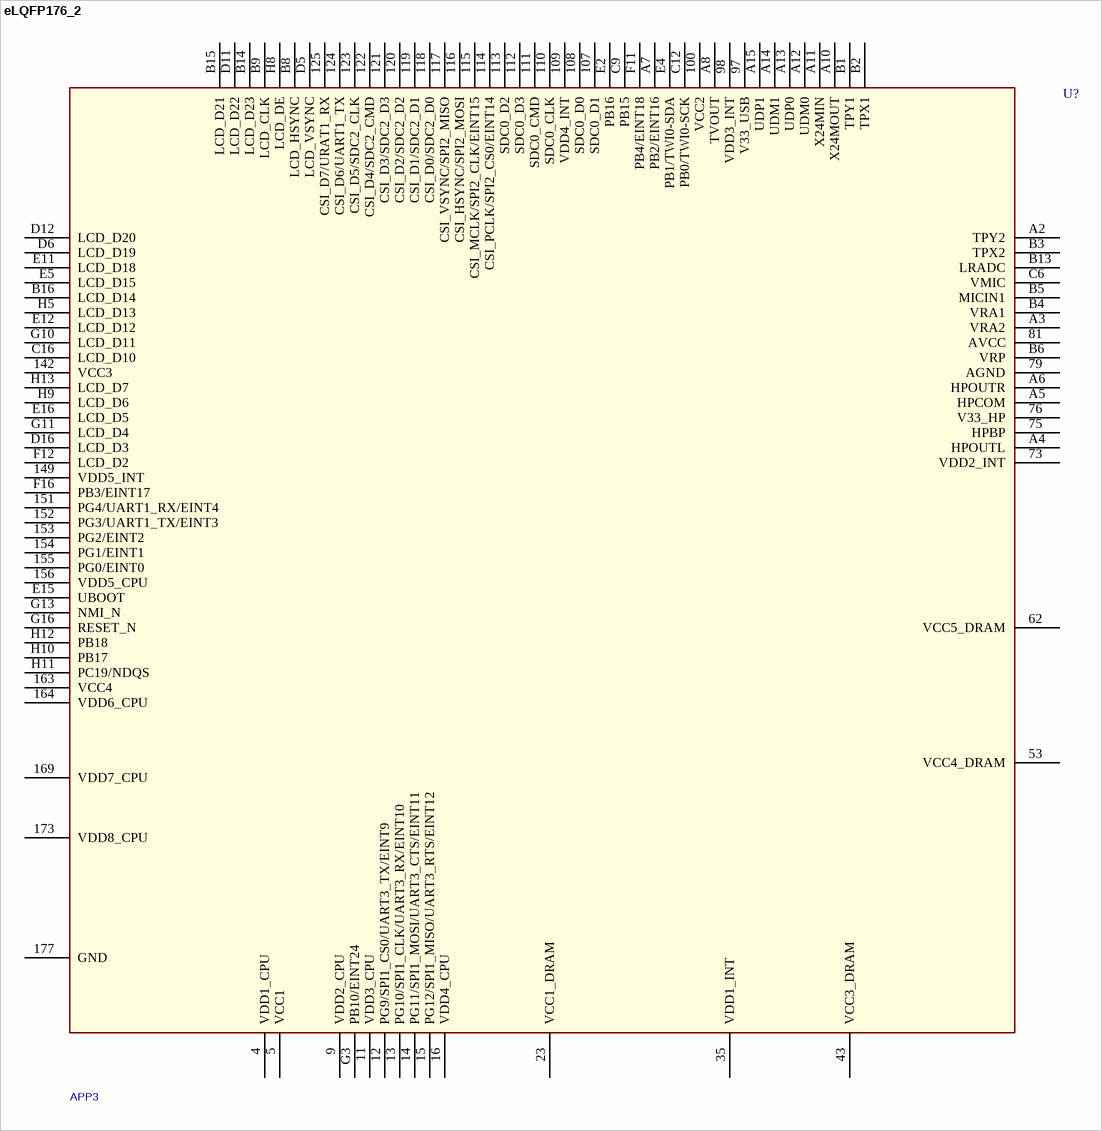
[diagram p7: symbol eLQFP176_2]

## eLQFP176_2
designator U?, comment APP3
Altium-Right: 630
pins: 4 VDD1_CPU, 5 VCC1, 9 VDD2_CPU, 11 VDD3_CPU, 12 PG9/SPI1_CS0/UART3_TX/EINT9, 13 PG10/SPI1_CLK/UART3_RX/EINT10, 14 PG11/SPI1_MOSI/UART3_CTS/EINT11, 15 PG12/SPI1_MISO/UART3_RTS/EINT12, 16 VDD4_CPU, 23 VCC1_DRAM, 35 VDD1_INT, 43 VCC3_DRAM, 53 VCC4_DRAM, 62 VCC5_DRAM, 73 VDD2_INT, 75 HPBP, 76 V33_HP, 79 AGND, 81 AVCC, 97 V33_USB, 98 VDD3_INT, 100 VCC2, 107 SDC0_D1, 108 SDC0_D0, 109 VDD4_INT, 110 SDC0_CLK, 111 SDC0_CMD, 112 SDC0_D3, 113 SDC0_D2, 114 CSI_PCLK/SPI2_CS0/EINT14, 115 CSI_MCLK/SPI2_CLK/EINT15, 116 CSI_HSYNC/SPI2_MOSI, 117 CSI_VSYNC/SPI2_MISO, 118 CSI_D0/SDC2_D0, 119 CSI_D1/SDC2_D1, 120 CSI_D2/SDC2_D2, 121 CSI_D3/SDC2_D3, 122 CSI_D4/SDC2_CMD, 123 CSI_D5/SDC2_CLK, 124 CSI_D6/UART1_TX, 125 CSI_D7/URAT1_RX, 142 VCC3, 149 VDD5_INT, 151 PG4/UART1_RX/EINT4, 152 PG3/UART1_TX/EINT3, 153 PG2/EINT2, 154 PG1/EINT1, 155 PG0/EINT0, 156 VDD5_CPU, 163 VCC4, 164 VDD6_CPU, 169 VDD7_CPU, 173 VDD8_CPU, 177 GND, A2 TPY2, A3 VRA2, A4 HPOUTL, A5 HPCOM, A6 HPOUTR, A7 PB2/EINT16, A8 TVOUT, A10 X24MOUT, A11 X24MIN, A12 UDM0, A13 UDP0, A14 UDM1, A15 UDP1, B1 TPY1, B2 TPX1, B3 TPX2, B4 VRA1, B5 MICIN1, B6 VRP, B8 LCD_HSYNC, B9 LCD_CLK, B13 LRADC, B14 LCD_D23, B15 LCD_D21, B16 LCD_D14, C6 VMIC, C9 PB15, C12 PB0/TWI0-SCK, C16 LCD_D10, D5 LCD_VSYNC, D6 LCD_D19, D11 LCD_D22, D12 LCD_D20, D16 LCD_D3, E2 PB16, E4 PB1/TWI0-SDA, E5 LCD_D15, E11 LCD_D18, E12 LCD_D12, E15 UBOOT, E16 LCD_D5, F11 PB4/EINT18, F12 LCD_D2, F16 PB3/EINT17, G3 PB10/EINT24, G10 LCD_D11, G11 LCD_D4, G13 NMI_N, G16 RESET_N, H5 LCD_D13, H8 LCD_DE, H9 LCD_D6, H10 PB17, H11 PC19/NDQS, H12 PB18, H13 LCD_D7

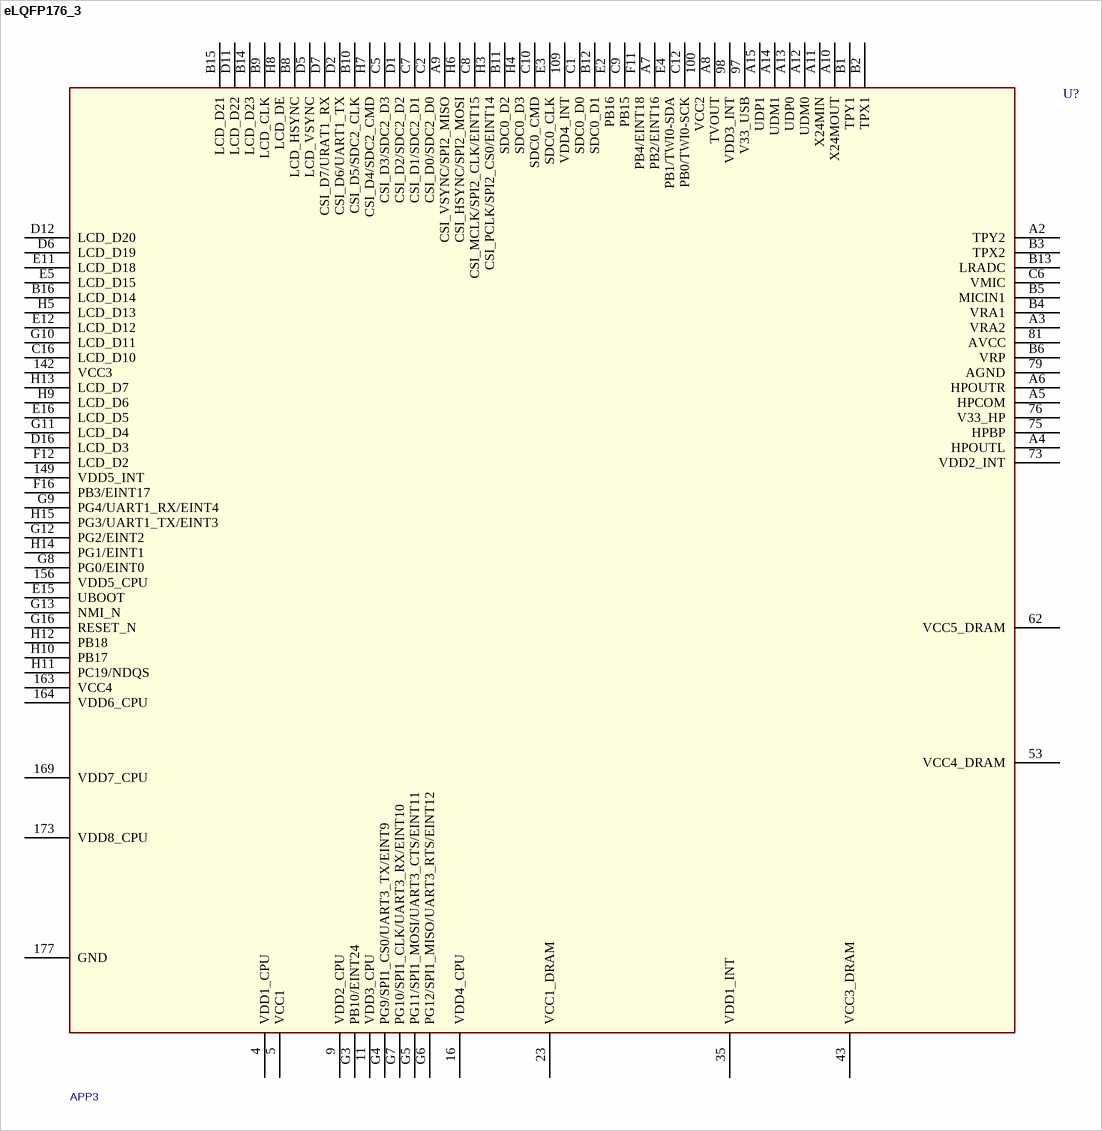
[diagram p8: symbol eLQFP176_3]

## eLQFP176_3
designator U?, comment APP3
Altium-Right: 630
pins: 4 VDD1_CPU, 5 VCC1, 9 VDD2_CPU, 11 VDD3_CPU, 16 VDD4_CPU, 23 VCC1_DRAM, 35 VDD1_INT, 43 VCC3_DRAM, 53 VCC4_DRAM, 62 VCC5_DRAM, 73 VDD2_INT, 75 HPBP, 76 V33_HP, 79 AGND, 81 AVCC, 97 V33_USB, 98 VDD3_INT, 100 VCC2, 109 VDD4_INT, 142 VCC3, 149 VDD5_INT, 156 VDD5_CPU, 163 VCC4, 164 VDD6_CPU, 169 VDD7_CPU, 173 VDD8_CPU, 177 GND, A2 TPY2, A3 VRA2, A4 HPOUTL, A5 HPCOM, A6 HPOUTR, A7 PB2/EINT16, A8 TVOUT, A9 CSI_VSYNC/SPI2_MISO, A10 X24MOUT, A11 X24MIN, A12 UDM0, A13 UDP0, A14 UDM1, A15 UDP1, B1 TPY1, B2 TPX1, B3 TPX2, B4 VRA1, B5 MICIN1, B6 VRP, B8 LCD_HSYNC, B9 LCD_CLK, B10 CSI_D5/SDC2_CLK, B11 SDC0_D2, B12 SDC0_D1, B13 LRADC, B14 LCD_D23, B15 LCD_D21, B16 LCD_D14, C1 SDC0_D0, C2 CSI_D0/SDC2_D0, C5 CSI_D3/SDC2_D3, C6 VMIC, C7 CSI_D1/SDC2_D1, C8 CSI_MCLK/SPI2_CLK/EINT15, C9 PB15, C10 SDC0_CMD, C12 PB0/TWI0-SCK, C16 LCD_D10, D1 CSI_D2/SDC2_D2, D2 CSI_D6/UART1_TX, D5 LCD_VSYNC, D6 LCD_D19, D7 CSI_D7/URAT1_RX, D11 LCD_D22, D12 LCD_D20, D16 LCD_D3, E2 PB16, E3 SDC0_CLK, E4 PB1/TWI0-SDA, E5 LCD_D15, E11 LCD_D18, E12 LCD_D12, E15 UBOOT, E16 LCD_D5, F11 PB4/EINT18, F12 LCD_D2, F16 PB3/EINT17, G3 PB10/EINT24, G4 PG9/SPI1_CS0/UART3_TX/EINT9, G5 PG11/SPI1_MOSI/UART3_CTS/EINT11, G6 PG12/SPI1_MISO/UART3_RTS/EINT12, G7 PG10/SPI1_CLK/UART3_RX/EINT10, G8 PG0/EINT0, G9 PG4/UART1_RX/EINT4, G10 LCD_D11, G11 LCD_D4, G12 PG2/EINT2, G13 NMI_N, G16 RESET_N, H3 CSI_PCLK/SPI2_CS0/EINT14, H4 SDC0_D3, H5 LCD_D13, H6 CSI_HSYNC/SPI2_MOSI, H7 CSI_D4/SDC2_CMD, H8 LCD_DE, H9 LCD_D6, H10 PB17, H11 PC19/NDQS, H12 PB18, H13 LCD_D7, H14 PG1/EINT1, H15 PG3/UART1_TX/EINT3

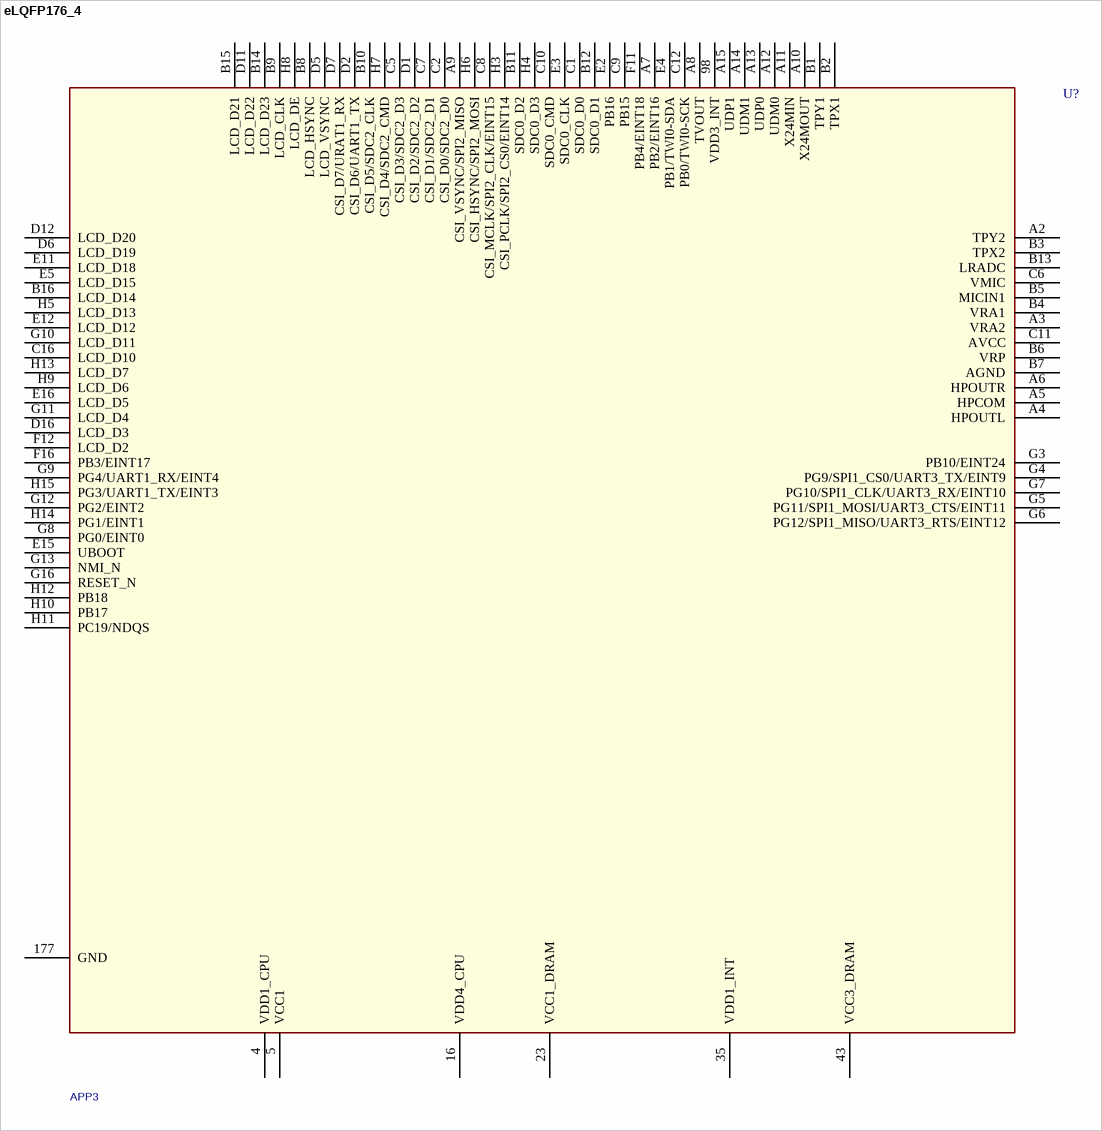
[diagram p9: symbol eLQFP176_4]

## eLQFP176_4
designator U?, comment APP3
Altium-Right: 630
pins: 4 VDD1_CPU, 5 VCC1, 16 VDD4_CPU, 23 VCC1_DRAM, 35 VDD1_INT, 43 VCC3_DRAM, 98 VDD3_INT, 177 GND, A2 TPY2, A3 VRA2, A4 HPOUTL, A5 HPCOM, A6 HPOUTR, A7 PB2/EINT16, A8 TVOUT, A9 CSI_VSYNC/SPI2_MISO, A10 X24MOUT, A11 X24MIN, A12 UDM0, A13 UDP0, A14 UDM1, A15 UDP1, B1 TPY1, B2 TPX1, B3 TPX2, B4 VRA1, B5 MICIN1, B6 VRP, B7 AGND, B8 LCD_HSYNC, B9 LCD_CLK, B10 CSI_D5/SDC2_CLK, B11 SDC0_D2, B12 SDC0_D1, B13 LRADC, B14 LCD_D23, B15 LCD_D21, B16 LCD_D14, C1 SDC0_D0, C2 CSI_D0/SDC2_D0, C5 CSI_D3/SDC2_D3, C6 VMIC, C7 CSI_D1/SDC2_D1, C8 CSI_MCLK/SPI2_CLK/EINT15, C9 PB15, C10 SDC0_CMD, C11 AVCC, C12 PB0/TWI0-SCK, C16 LCD_D10, D1 CSI_D2/SDC2_D2, D2 CSI_D6/UART1_TX, D5 LCD_VSYNC, D6 LCD_D19, D7 CSI_D7/URAT1_RX, D11 LCD_D22, D12 LCD_D20, D16 LCD_D3, E2 PB16, E3 SDC0_CLK, E4 PB1/TWI0-SDA, E5 LCD_D15, E11 LCD_D18, E12 LCD_D12, E15 UBOOT, E16 LCD_D5, F11 PB4/EINT18, F12 LCD_D2, F16 PB3/EINT17, G3 PB10/EINT24, G4 PG9/SPI1_CS0/UART3_TX/EINT9, G5 PG11/SPI1_MOSI/UART3_CTS/EINT11, G6 PG12/SPI1_MISO/UART3_RTS/EINT12, G7 PG10/SPI1_CLK/UART3_RX/EINT10, G8 PG0/EINT0, G9 PG4/UART1_RX/EINT4, G10 LCD_D11, G11 LCD_D4, G12 PG2/EINT2, G13 NMI_N, G16 RESET_N, H3 CSI_PCLK/SPI2_CS0/EINT14, H4 SDC0_D3, H5 LCD_D13, H6 CSI_HSYNC/SPI2_MOSI, H7 CSI_D4/SDC2_CMD, H8 LCD_DE, H9 LCD_D6, H10 PB17, H11 PC19/NDQS, H12 PB18, H13 LCD_D7, H14 PG1/EINT1, H15 PG3/UART1_TX/EINT3

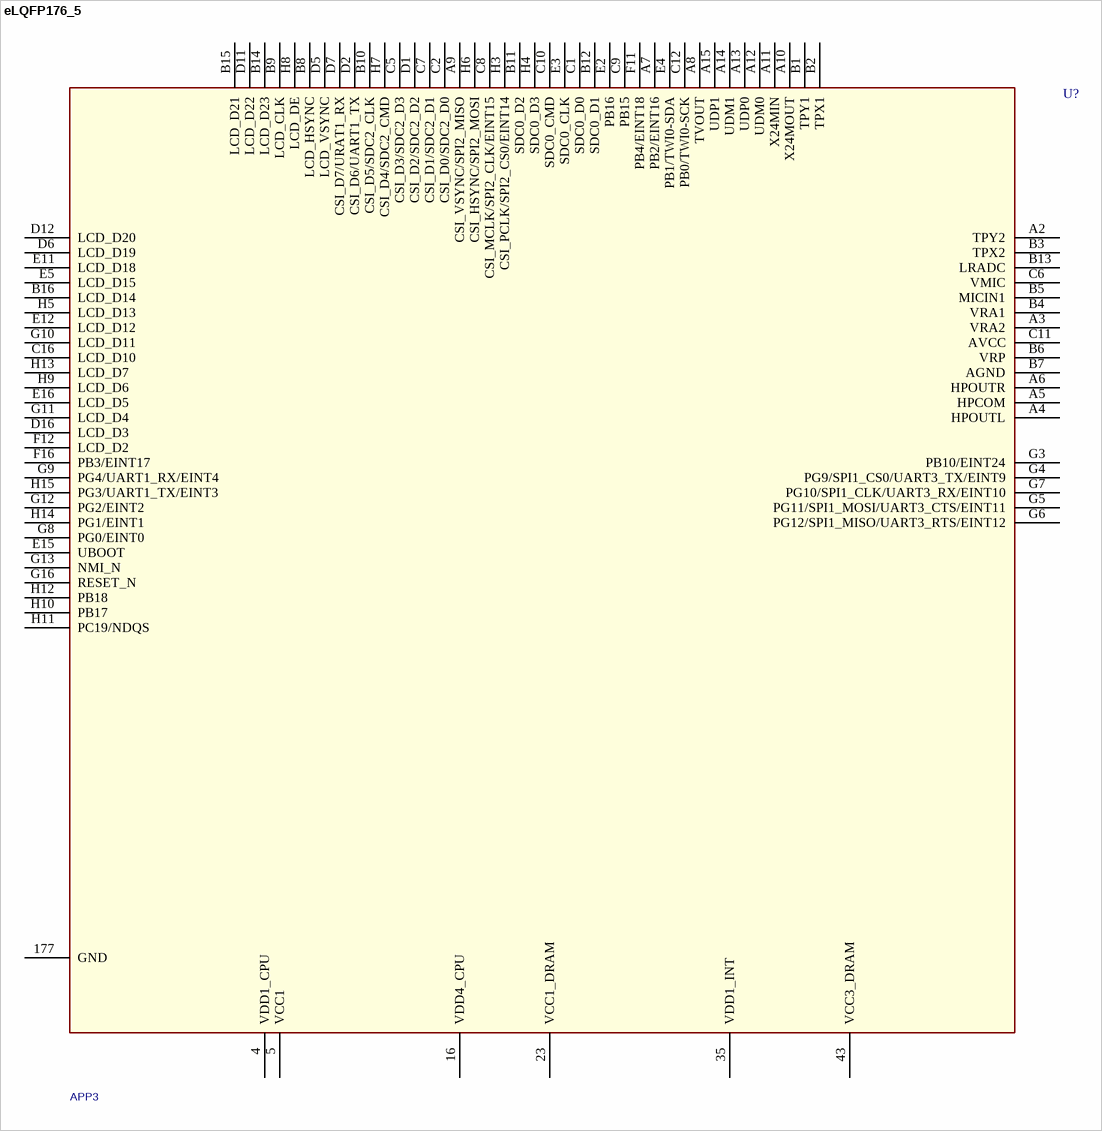
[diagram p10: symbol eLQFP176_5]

## eLQFP176_5
designator U?, comment APP3
Altium-Right: 630
pins: 4 VDD1_CPU, 5 VCC1, 16 VDD4_CPU, 23 VCC1_DRAM, 35 VDD1_INT, 43 VCC3_DRAM, 177 GND, A2 TPY2, A3 VRA2, A4 HPOUTL, A5 HPCOM, A6 HPOUTR, A7 PB2/EINT16, A8 TVOUT, A9 CSI_VSYNC/SPI2_MISO, A10 X24MOUT, A11 X24MIN, A12 UDM0, A13 UDP0, A14 UDM1, A15 UDP1, B1 TPY1, B2 TPX1, B3 TPX2, B4 VRA1, B5 MICIN1, B6 VRP, B7 AGND, B8 LCD_HSYNC, B9 LCD_CLK, B10 CSI_D5/SDC2_CLK, B11 SDC0_D2, B12 SDC0_D1, B13 LRADC, B14 LCD_D23, B15 LCD_D21, B16 LCD_D14, C1 SDC0_D0, C2 CSI_D0/SDC2_D0, C5 CSI_D3/SDC2_D3, C6 VMIC, C7 CSI_D1/SDC2_D1, C8 CSI_MCLK/SPI2_CLK/EINT15, C9 PB15, C10 SDC0_CMD, C11 AVCC, C12 PB0/TWI0-SCK, C16 LCD_D10, D1 CSI_D2/SDC2_D2, D2 CSI_D6/UART1_TX, D5 LCD_VSYNC, D6 LCD_D19, D7 CSI_D7/URAT1_RX, D11 LCD_D22, D12 LCD_D20, D16 LCD_D3, E2 PB16, E3 SDC0_CLK, E4 PB1/TWI0-SDA, E5 LCD_D15, E11 LCD_D18, E12 LCD_D12, E15 UBOOT, E16 LCD_D5, F11 PB4/EINT18, F12 LCD_D2, F16 PB3/EINT17, G3 PB10/EINT24, G4 PG9/SPI1_CS0/UART3_TX/EINT9, G5 PG11/SPI1_MOSI/UART3_CTS/EINT11, G6 PG12/SPI1_MISO/UART3_RTS/EINT12, G7 PG10/SPI1_CLK/UART3_RX/EINT10, G8 PG0/EINT0, G9 PG4/UART1_RX/EINT4, G10 LCD_D11, G11 LCD_D4, G12 PG2/EINT2, G13 NMI_N, G16 RESET_N, H3 CSI_PCLK/SPI2_CS0/EINT14, H4 SDC0_D3, H5 LCD_D13, H6 CSI_HSYNC/SPI2_MOSI, H7 CSI_D4/SDC2_CMD, H8 LCD_DE, H9 LCD_D6, H10 PB17, H11 PC19/NDQS, H12 PB18, H13 LCD_D7, H14 PG1/EINT1, H15 PG3/UART1_TX/EINT3

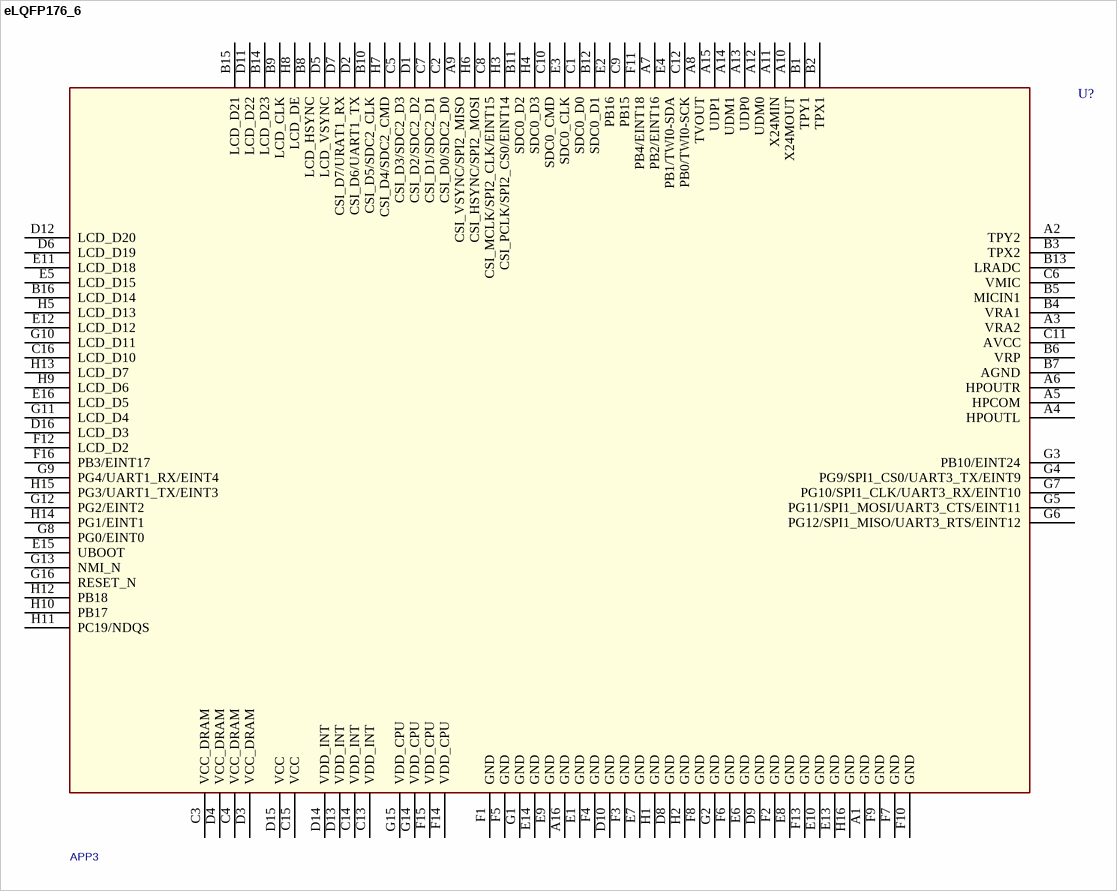
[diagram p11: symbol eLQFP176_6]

## eLQFP176_6
designator U?, comment APP3
Altium-Right: 640; Altium-Bottom: 470
pins: A1 GND (power), A2 TPY2, A3 VRA2, A4 HPOUTL, A5 HPCOM, A6 HPOUTR, A7 PB2/EINT16, A8 TVOUT, A9 CSI_VSYNC/SPI2_MISO, A10 X24MOUT, A11 X24MIN, A12 UDM0, A13 UDP0, A14 UDM1, A15 UDP1, A16 GND (power), B1 TPY1, B2 TPX1, B3 TPX2, B4 VRA1, B5 MICIN1, B6 VRP, B7 AGND, B8 LCD_HSYNC, B9 LCD_CLK, B10 CSI_D5/SDC2_CLK, B11 SDC0_D2, B12 SDC0_D1, B13 LRADC, B14 LCD_D23, B15 LCD_D21, B16 LCD_D14, C1 SDC0_D0, C2 CSI_D0/SDC2_D0, C3 VCC_DRAM (power), C4 VCC_DRAM (power), C5 CSI_D3/SDC2_D3, C6 VMIC, C7 CSI_D1/SDC2_D1, C8 CSI_MCLK/SPI2_CLK/EINT15, C9 PB15, C10 SDC0_CMD, C11 AVCC, C12 PB0/TWI0-SCK, C13 VDD_INT (power), C14 VDD_INT (power), C15 VCC (power), C16 LCD_D10, D1 CSI_D2/SDC2_D2, D2 CSI_D6/UART1_TX, D3 VCC_DRAM (power), D4 VCC_DRAM (power), D5 LCD_VSYNC, D6 LCD_D19, D7 CSI_D7/URAT1_RX, D8 GND (power), D9 GND (power), D10 GND (power), D11 LCD_D22, D12 LCD_D20, D13 VDD_INT (power), D14 VDD_INT (power), D15 VCC (power), D16 LCD_D3, E1 GND (power), E2 PB16, E3 SDC0_CLK, E4 PB1/TWI0-SDA, E5 LCD_D15, E6 GND (power), E7 GND (power), E8 GND (power), E9 GND (power), E10 GND (power), E11 LCD_D18, E12 LCD_D12, E13 GND (power), E14 GND (power), E15 UBOOT, E16 LCD_D5, F1 GND (power), F2 GND (power), F3 GND (power), F4 GND (power), F5 GND (power), F6 GND (power), F7 GND (power), F8 GND (power), F9 GND (power), F10 GND (power), F11 PB4/EINT18, F12 LCD_D2, F13 GND (power), F14 VDD_CPU (power), F15 VDD_CPU (power), F16 PB3/EINT17, G1 GND (power), G2 GND (power), G3 PB10/EINT24, G4 PG9/SPI1_CS0/UART3_TX/EINT9, G5 PG11/SPI1_MOSI/UART3_CTS/EINT11, G6 PG12/SPI1_MISO/UART3_RTS/EINT12, G7 PG10/SPI1_CLK/UART3_RX/EINT10, G8 PG0/EINT0, G9 PG4/UART1_RX/EINT4, G10 LCD_D11, G11 LCD_D4, G12 PG2/EINT2, G13 NMI_N, G14 VDD_CPU (power), G15 VDD_CPU (power), G16 RESET_N, H1 GND (power), H2 GND (power), H3 CSI_PCLK/SPI2_CS0/EINT14, H4 SDC0_D3, H5 LCD_D13, H6 CSI_HSYNC/SPI2_MOSI, H7 CSI_D4/SDC2_CMD, H8 LCD_DE, H9 LCD_D6, H10 PB17, H11 PC19/NDQS, H12 PB18, H13 LCD_D7, H14 PG1/EINT1, H15 PG3/UART1_TX/EINT3, H16 GND (power)

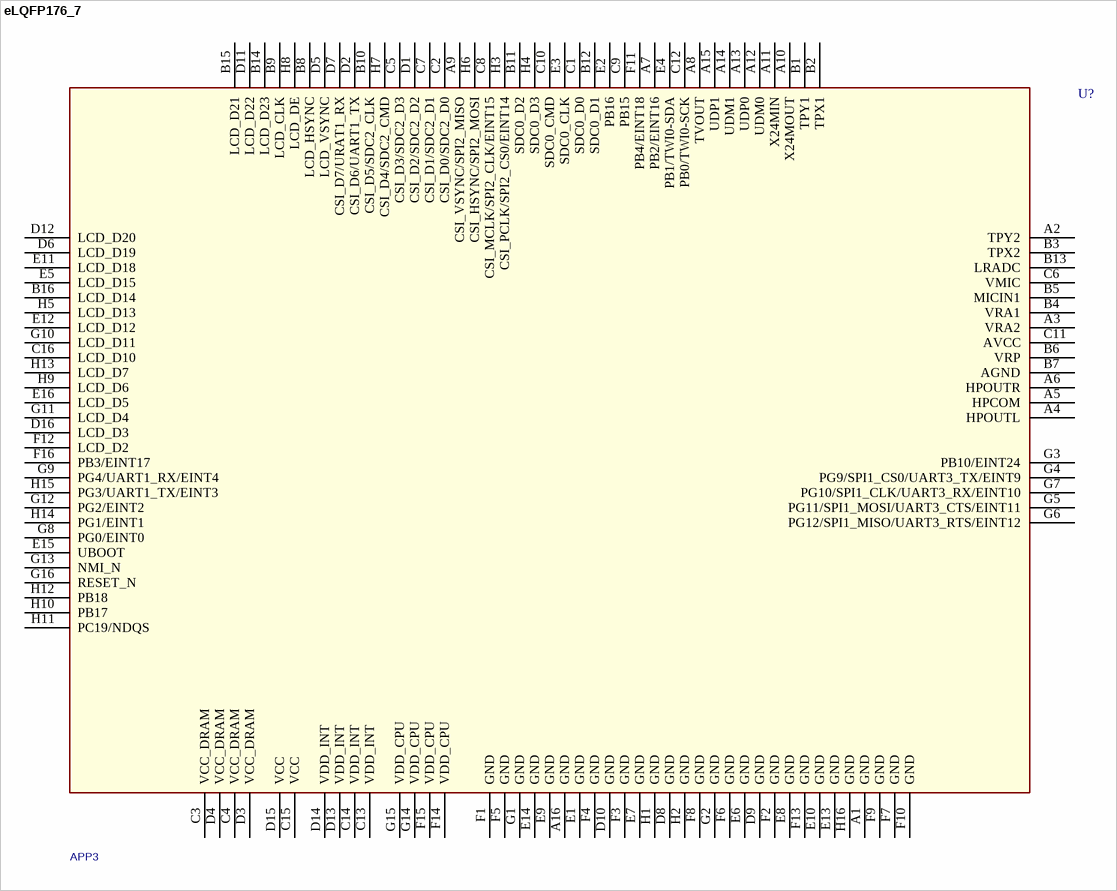
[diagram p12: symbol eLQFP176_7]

## eLQFP176_7
designator U?, comment APP3
Altium-Right: 640; Altium-Bottom: 470
pins: A1 GND (power), A2 TPY2, A3 VRA2, A4 HPOUTL, A5 HPCOM, A6 HPOUTR, A7 PB2/EINT16, A8 TVOUT, A9 CSI_VSYNC/SPI2_MISO, A10 X24MOUT, A11 X24MIN, A12 UDM0, A13 UDP0, A14 UDM1, A15 UDP1, A16 GND (power), B1 TPY1, B2 TPX1, B3 TPX2, B4 VRA1, B5 MICIN1, B6 VRP, B7 AGND, B8 LCD_HSYNC, B9 LCD_CLK, B10 CSI_D5/SDC2_CLK, B11 SDC0_D2, B12 SDC0_D1, B13 LRADC, B14 LCD_D23, B15 LCD_D21, B16 LCD_D14, C1 SDC0_D0, C2 CSI_D0/SDC2_D0, C3 VCC_DRAM (power), C4 VCC_DRAM (power), C5 CSI_D3/SDC2_D3, C6 VMIC, C7 CSI_D1/SDC2_D1, C8 CSI_MCLK/SPI2_CLK/EINT15, C9 PB15, C10 SDC0_CMD, C11 AVCC, C12 PB0/TWI0-SCK, C13 VDD_INT (power), C14 VDD_INT (power), C15 VCC (power), C16 LCD_D10, D1 CSI_D2/SDC2_D2, D2 CSI_D6/UART1_TX, D3 VCC_DRAM (power), D4 VCC_DRAM (power), D5 LCD_VSYNC, D6 LCD_D19, D7 CSI_D7/URAT1_RX, D8 GND (power), D9 GND (power), D10 GND (power), D11 LCD_D22, D12 LCD_D20, D13 VDD_INT (power), D14 VDD_INT (power), D15 VCC (power), D16 LCD_D3, E1 GND (power), E2 PB16, E3 SDC0_CLK, E4 PB1/TWI0-SDA, E5 LCD_D15, E6 GND (power), E7 GND (power), E8 GND (power), E9 GND (power), E10 GND (power), E11 LCD_D18, E12 LCD_D12, E13 GND (power), E14 GND (power), E15 UBOOT, E16 LCD_D5, F1 GND (power), F2 GND (power), F3 GND (power), F4 GND (power), F5 GND (power), F6 GND (power), F7 GND (power), F8 GND (power), F9 GND (power), F10 GND (power), F11 PB4/EINT18, F12 LCD_D2, F13 GND (power), F14 VDD_CPU (power), F15 VDD_CPU (power), F16 PB3/EINT17, G1 GND (power), G2 GND (power), G3 PB10/EINT24, G4 PG9/SPI1_CS0/UART3_TX/EINT9, G5 PG11/SPI1_MOSI/UART3_CTS/EINT11, G6 PG12/SPI1_MISO/UART3_RTS/EINT12, G7 PG10/SPI1_CLK/UART3_RX/EINT10, G8 PG0/EINT0, G9 PG4/UART1_RX/EINT4, G10 LCD_D11, G11 LCD_D4, G12 PG2/EINT2, G13 NMI_N, G14 VDD_CPU (power), G15 VDD_CPU (power), G16 RESET_N, H1 GND (power), H2 GND (power), H3 CSI_PCLK/SPI2_CS0/EINT14, H4 SDC0_D3, H5 LCD_D13, H6 CSI_HSYNC/SPI2_MOSI, H7 CSI_D4/SDC2_CMD, H8 LCD_DE, H9 LCD_D6, H10 PB17, H11 PC19/NDQS, H12 PB18, H13 LCD_D7, H14 PG1/EINT1, H15 PG3/UART1_TX/EINT3, H16 GND (power)

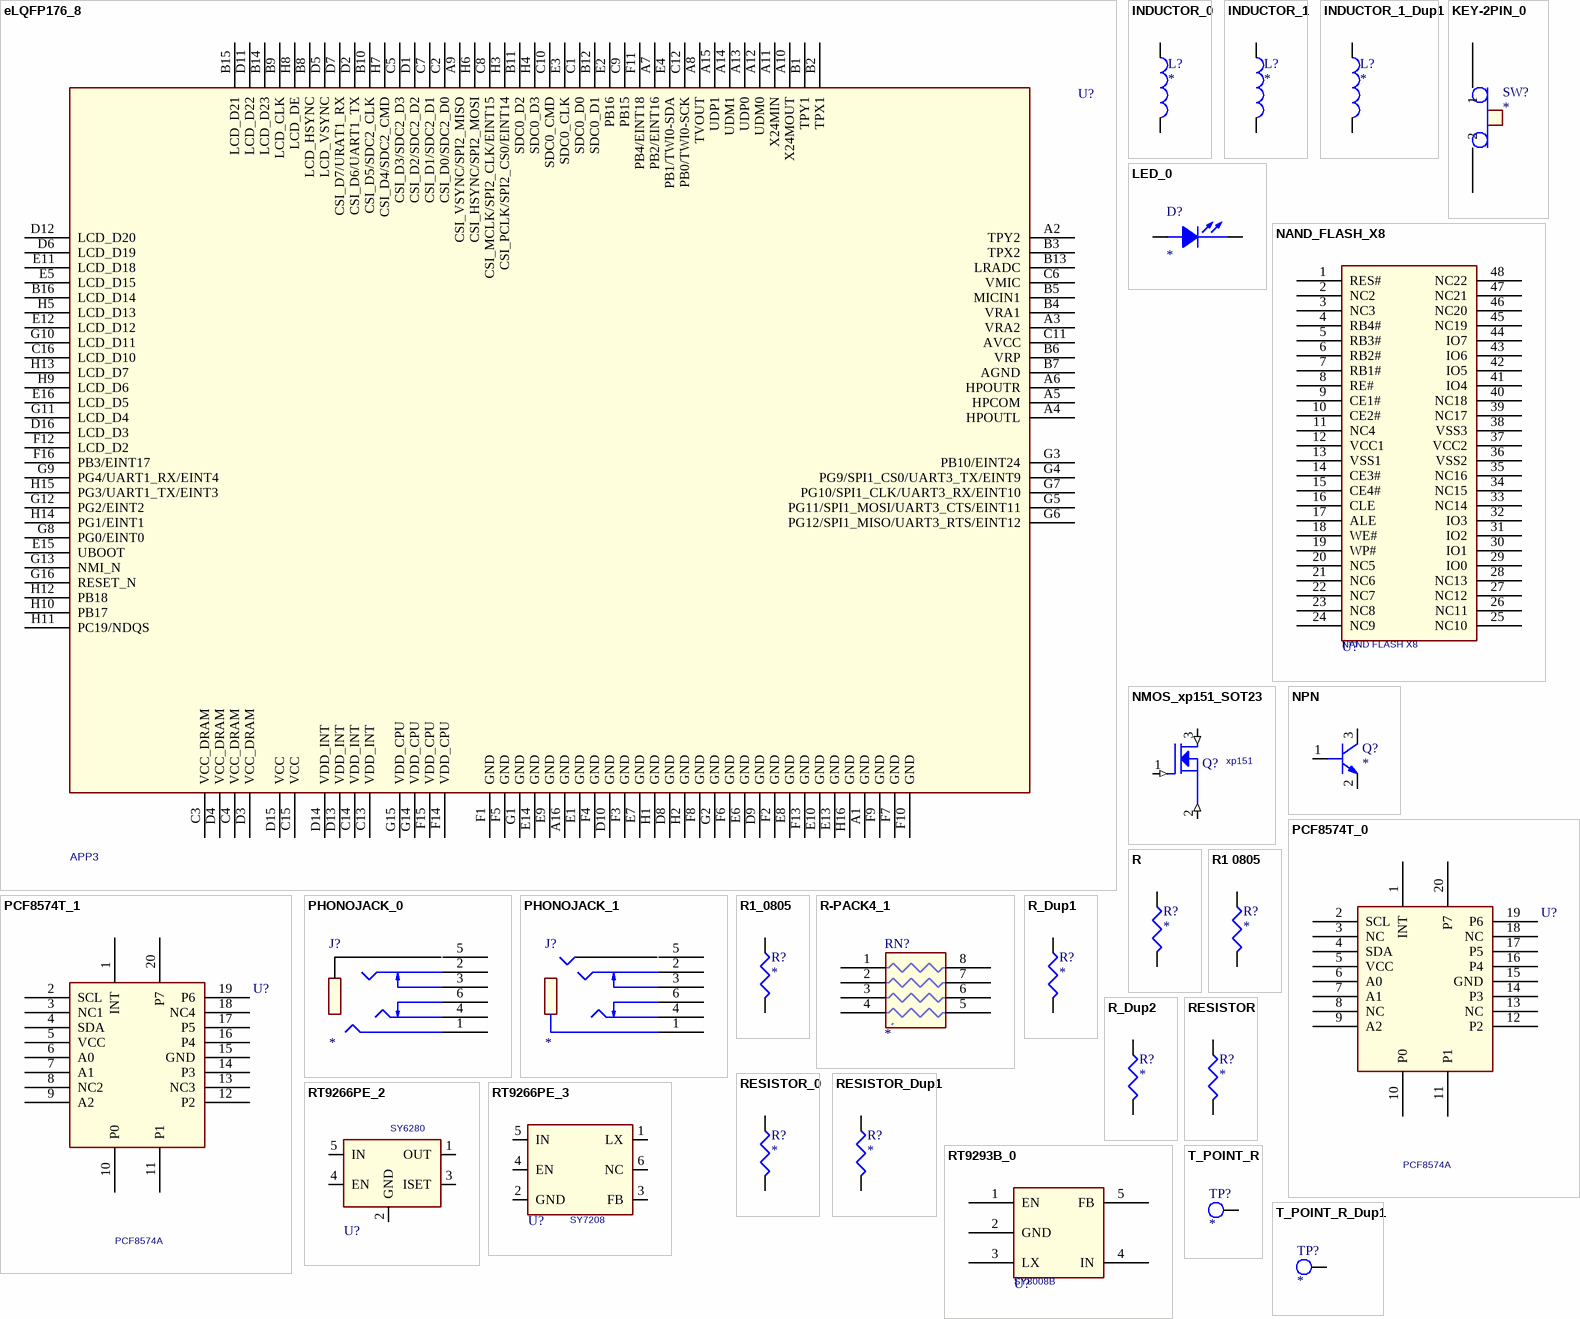
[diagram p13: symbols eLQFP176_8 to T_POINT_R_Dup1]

## eLQFP176_8
designator U?, comment APP3
Altium-Right: 640; Altium-Bottom: 470
pins: A1 GND (power), A2 TPY2, A3 VRA2, A4 HPOUTL, A5 HPCOM, A6 HPOUTR, A7 PB2/EINT16, A8 TVOUT, A9 CSI_VSYNC/SPI2_MISO, A10 X24MOUT, A11 X24MIN, A12 UDM0, A13 UDP0, A14 UDM1, A15 UDP1, A16 GND (power), B1 TPY1, B2 TPX1, B3 TPX2, B4 VRA1, B5 MICIN1, B6 VRP, B7 AGND, B8 LCD_HSYNC, B9 LCD_CLK, B10 CSI_D5/SDC2_CLK, B11 SDC0_D2, B12 SDC0_D1, B13 LRADC, B14 LCD_D23, B15 LCD_D21, B16 LCD_D14, C1 SDC0_D0, C2 CSI_D0/SDC2_D0, C3 VCC_DRAM (power), C4 VCC_DRAM (power), C5 CSI_D3/SDC2_D3, C6 VMIC, C7 CSI_D1/SDC2_D1, C8 CSI_MCLK/SPI2_CLK/EINT15, C9 PB15, C10 SDC0_CMD, C11 AVCC, C12 PB0/TWI0-SCK, C13 VDD_INT (power), C14 VDD_INT (power), C15 VCC (power), C16 LCD_D10, D1 CSI_D2/SDC2_D2, D2 CSI_D6/UART1_TX, D3 VCC_DRAM (power), D4 VCC_DRAM (power), D5 LCD_VSYNC, D6 LCD_D19, D7 CSI_D7/URAT1_RX, D8 GND (power), D9 GND (power), D10 GND (power), D11 LCD_D22, D12 LCD_D20, D13 VDD_INT (power), D14 VDD_INT (power), D15 VCC (power), D16 LCD_D3, E1 GND (power), E2 PB16, E3 SDC0_CLK, E4 PB1/TWI0-SDA, E5 LCD_D15, E6 GND (power), E7 GND (power), E8 GND (power), E9 GND (power), E10 GND (power), E11 LCD_D18, E12 LCD_D12, E13 GND (power), E14 GND (power), E15 UBOOT, E16 LCD_D5, F1 GND (power), F2 GND (power), F3 GND (power), F4 GND (power), F5 GND (power), F6 GND (power), F7 GND (power), F8 GND (power), F9 GND (power), F10 GND (power), F11 PB4/EINT18, F12 LCD_D2, F13 GND (power), F14 VDD_CPU (power), F15 VDD_CPU (power), F16 PB3/EINT17, G1 GND (power), G2 GND (power), G3 PB10/EINT24, G4 PG9/SPI1_CS0/UART3_TX/EINT9, G5 PG11/SPI1_MOSI/UART3_CTS/EINT11, G6 PG12/SPI1_MISO/UART3_RTS/EINT12, G7 PG10/SPI1_CLK/UART3_RX/EINT10, G8 PG0/EINT0, G9 PG4/UART1_RX/EINT4, G10 LCD_D11, G11 LCD_D4, G12 PG2/EINT2, G13 NMI_N, G14 VDD_CPU (power), G15 VDD_CPU (power), G16 RESET_N, H1 GND (power), H2 GND (power), H3 CSI_PCLK/SPI2_CS0/EINT14, H4 SDC0_D3, H5 LCD_D13, H6 CSI_HSYNC/SPI2_MOSI, H7 CSI_D4/SDC2_CMD, H8 LCD_DE, H9 LCD_D6, H10 PB17, H11 PC19/NDQS, H12 PB18, H13 LCD_D7, H14 PG1/EINT1, H15 PG3/UART1_TX/EINT3, H16 GND (power)

## INDUCTOR_0
designator L?
Altium-Right: 20; Altium-Bottom: 40
pins: 1, 2

## INDUCTOR_1
designator L?
Altium-Right: 20; Altium-Bottom: 40
pins: 1, 2

## INDUCTOR_1_Dup1
designator L?
Altium-Right: 20; Altium-Bottom: 40
pins: 1, 2

## KEY-2PIN_0
designator SW?
Altium-Right: 40
footprint KEY-2
pins: 1, 2

## LED_0
designator D?
Altium-Right: 40; Altium-Bottom: 20
pins: 1 ANODE, 2 CATHODE

## NAND_FLASH_X8
designator U?, comment NAND FLASH X8
Altium-Right: 90; Altium-Bottom: 250
footprint TSOP-48
pins: 1 RES#, 2 NC2, 3 NC3, 4 RB4#, 5 RB3#, 6 RB2#, 7 RB1#, 8 RE#, 9 CE1#, 10 CE2#, 11 NC4, 12 VCC1, 13 VSS1, 14 CE3#, 15 CE4#, 16 CLE, 17 ALE, 18 WE#, 19 WP#, 20 NC5, 21 NC6, 22 NC7, 23 NC8, 24 NC9, 25 NC10, 26 NC11, 27 NC12, 28 NC13, 29 IO0, 30 IO1, 31 IO2, 32 IO3, 33 NC14, 34 NC15, 35 NC16, 36 VSS2, 37 VCC2, 38 VSS3, 39 NC17, 40 NC18, 41 IO4, 42 IO5, 43 IO6, 44 IO7, 45 NC19, 46 NC20, 47 NC21, 48 NC22

## NMOS_xp151_SOT23
designator Q?, comment xp151
Altium-Right: 30; Altium-Bottom: 40
footprint sot-23
pins: 1 GATE (in), 2 SOURCE (in), 3 DRAIN (in)

## NPN
designator Q?
Altium-Right: 20
pins: 1 B, 2 E, 3 C

## PCF8574T_0
designator U?, comment PCF8574A
Altium-Right: 90; Altium-Bottom: 110
footprint SO16
pins: 1 INT, 2 SCL, 3 NC, 4 SDA, 5 VCC, 6 A0, 7 A1, 8 NC, 9 A2, 10 P0, 11 P1, 12 P2, 13 NC, 14 P3, 15 GND, 16 P4, 17 P5, 18 NC, 19 P6, 20 P7

## PCF8574T_1
designator U?, comment PCF8574A
Altium-Right: 90; Altium-Bottom: 110
footprint SO16
pins: 1 INT, 2 SCL, 3 NC1, 4 SDA, 5 VCC, 6 A0, 7 A1, 8 NC2, 9 A2, 10 P0, 11 P1, 12 P2, 13 NC3, 14 P3, 15 GND, 16 P4, 17 P5, 18 NC4, 19 P6, 20 P7

## PHONOJACK_0
designator J?
Altium-Right: 80; Altium-Bottom: 70
footprint TSH-3865D
pins: 1, 2, 3, 4, 5, 6

## PHONOJACK_1
designator J?
Altium-Right: 80; Altium-Bottom: 70
footprint TSH-3865D
pins: 1, 2, 3, 4, 5, 6

## R
designator R?
Altium-Right: 20; Altium-Bottom: 30
pins: 1, 2

## R1 0805
designator R?
Altium-Right: 20; Altium-Bottom: 30
footprint 0805
pins: 1, 2

## R1_0805
designator R?
Altium-Right: 20; Altium-Bottom: 30
footprint 0805
pins: 1, 2

## R-PACK4_1
designator RN?
Altium-Right: 40; Altium-Bottom: 50
pins: 1 R1, 2 R2, 3 R3, 4 R4, 5 R5, 6 R6, 7 R7, 8 R8

## R_Dup1
designator R?
Altium-Right: 20; Altium-Bottom: 30
pins: 1, 2

## R_Dup2
designator R?
Altium-Right: 20; Altium-Bottom: 30
pins: 1, 2

## RESISTOR
designator R?
Altium-Right: 20; Altium-Bottom: 30
pins: 1, 2

## RESISTOR_0
designator R?
Altium-Right: 20; Altium-Bottom: 30
footprint R0603
pins: 1, 2

## RESISTOR_Dup1
designator R?
Altium-Right: 20; Altium-Bottom: 30
pins: 1, 2

## RT9266PE_2
designator U?, comment SY6280
Altium-Right: 65; Altium-Bottom: 45
footprint SOT23-6
pins: 1 OUT, 2 GND, 3 ISET, 4 EN, 5 IN

## RT9266PE_3
designator U?, comment SY7208
Altium-Right: 70; Altium-Bottom: 60
footprint SOT23-6
pins: 1 LX, 2 GND, 3 FB, 4 EN, 5 IN, 6 NC

## RT9293B_0
designator U?, comment SY8008B
Altium-Right: 60
footprint TSOT-23-6
pins: 1 EN, 2 GND, 3 LX, 4 IN, 5 FB

## T_POINT_R
designator TP?
Altium-Right: 10; Altium-Bottom: 20
pins: 1 TP

## T_POINT_R_Dup1
designator TP?
Altium-Right: 10; Altium-Bottom: 20
pins: 1 TP

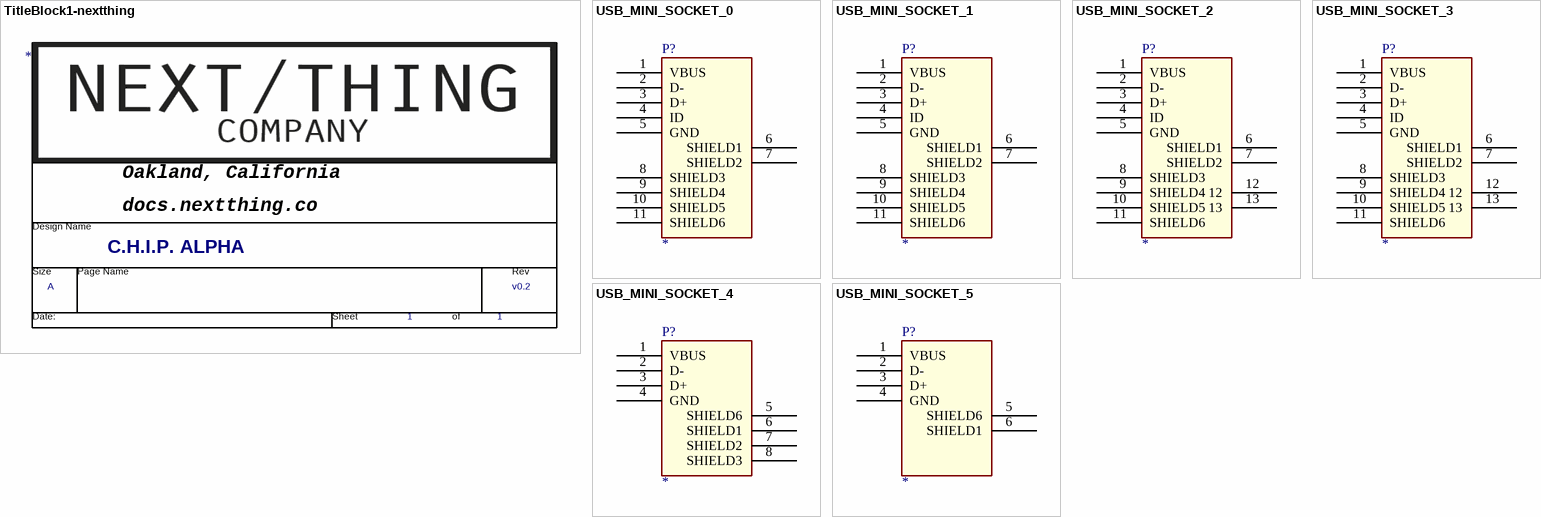
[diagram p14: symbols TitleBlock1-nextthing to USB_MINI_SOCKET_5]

## TitleBlock1-nextthing
designator *  Page Count: 1  Page Size: A  Title: C.H.I.P. ALPHA  RevCode: v0.2  (graphical)
Altium-Right: 350; Altium-Bottom: 190

## USB_MINI_SOCKET_0
designator P?
Altium-Right: 60; Altium-Bottom: 120
footprint USB_MINI_AB
pins: 1 VBUS, 2 D-, 3 D+, 4 ID, 5 GND, 6 SHIELD1, 7 SHIELD2, 8 SHIELD3, 9 SHIELD4, 10 SHIELD5, 11 SHIELD6

## USB_MINI_SOCKET_1
designator P?
Altium-Right: 60; Altium-Bottom: 120
footprint USB_MINI_AB
pins: 1 VBUS, 2 D-, 3 D+, 4 ID, 5 GND, 6 SHIELD1, 7 SHIELD2, 8 SHIELD3, 9 SHIELD4, 10 SHIELD5, 11 SHIELD6

## USB_MINI_SOCKET_2
designator P?
Altium-Right: 60; Altium-Bottom: 120
footprint USB_MINI_AB
pins: 1 VBUS, 2 D-, 3 D+, 4 ID, 5 GND, 6 SHIELD1, 7 SHIELD2, 8 SHIELD3, 9 SHIELD4, 10 SHIELD5, 11 SHIELD6, 12, 13

## USB_MINI_SOCKET_3
designator P?
Altium-Right: 60; Altium-Bottom: 120
footprint USB_MINI_AB
pins: 1 VBUS, 2 D-, 3 D+, 4 ID, 5 GND, 6 SHIELD1, 7 SHIELD2, 8 SHIELD3, 9 SHIELD4, 10 SHIELD5, 11 SHIELD6, 12, 13

## USB_MINI_SOCKET_4
designator P?
Altium-Right: 60; Altium-Bottom: 90
footprint USB_MINI_AB
pins: 1 VBUS, 2 D-, 3 D+, 4 GND, 5 SHIELD6, 6 SHIELD1, 7 SHIELD2, 8 SHIELD3

## USB_MINI_SOCKET_5
designator P?
Altium-Right: 60; Altium-Bottom: 90
footprint USB_MINI_AB
pins: 1 VBUS, 2 D-, 3 D+, 4 GND, 5 SHIELD6, 6 SHIELD1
